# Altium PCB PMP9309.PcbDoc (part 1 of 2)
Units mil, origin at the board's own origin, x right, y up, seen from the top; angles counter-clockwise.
Board outline 7000 x 6500 mil, 4 copper layers (Top Layer, MidLayer1, MidLayer2, Bottom Layer), stack 90 mil thick; 176 components, 71 nets, 1187 pads, 29 vias.
Unrouted connection lines stored in the file: 1.
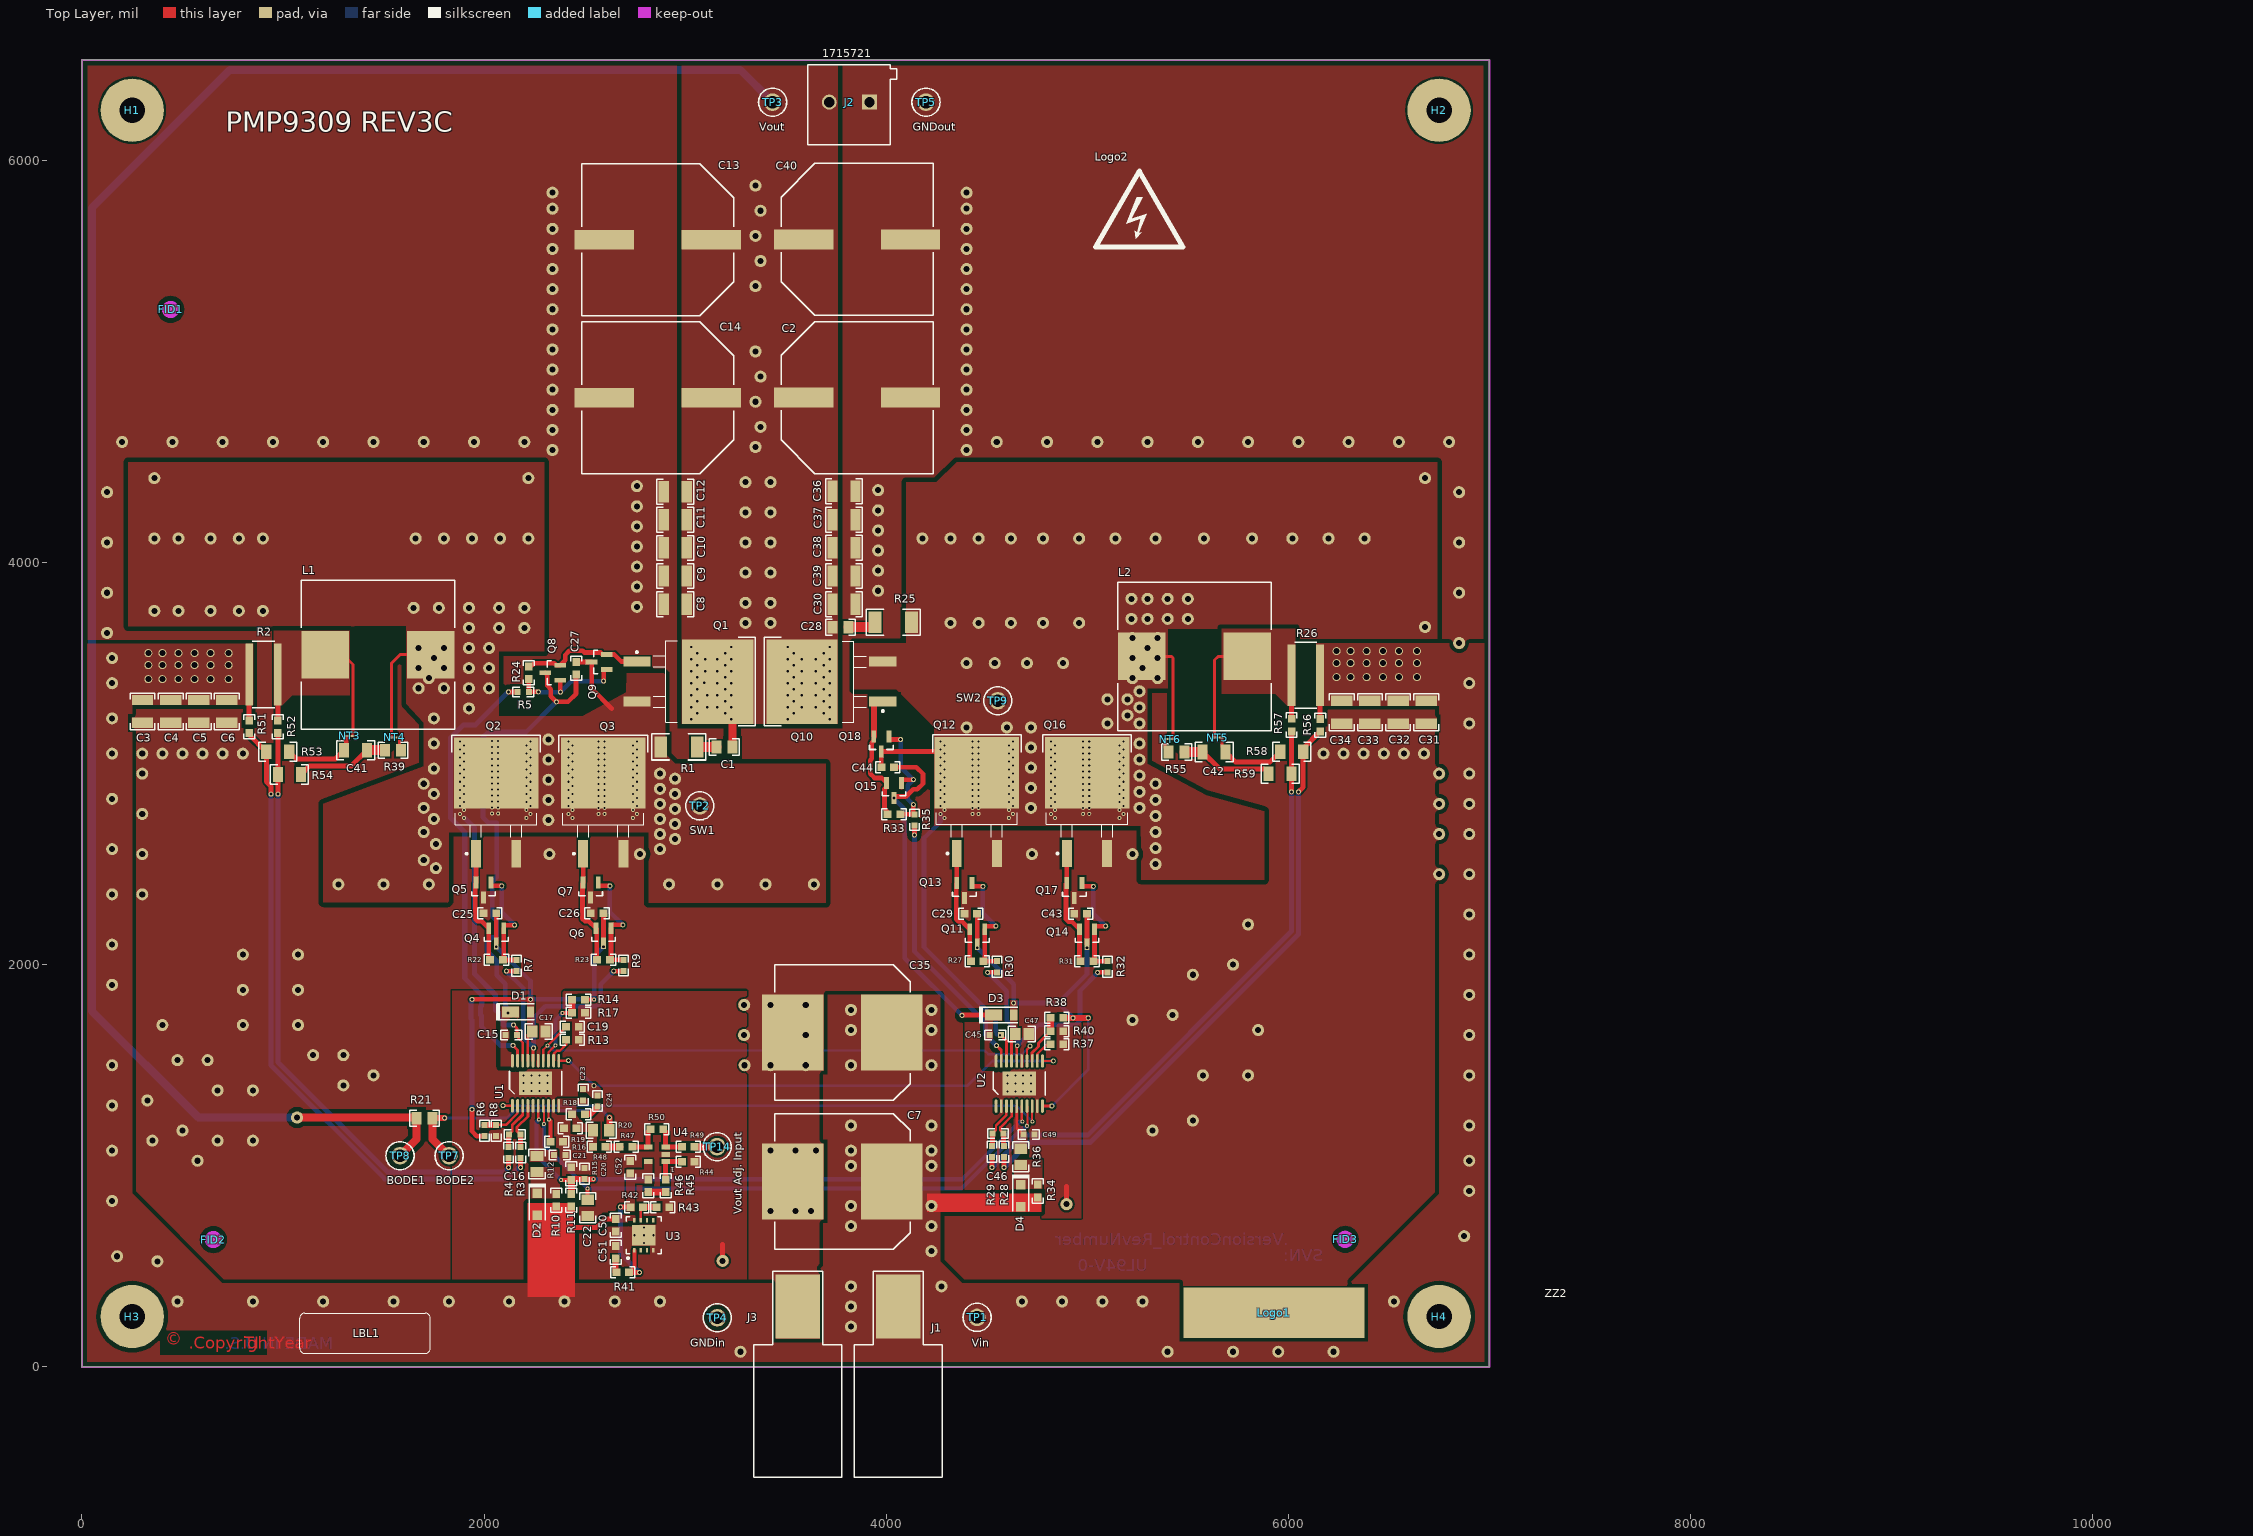
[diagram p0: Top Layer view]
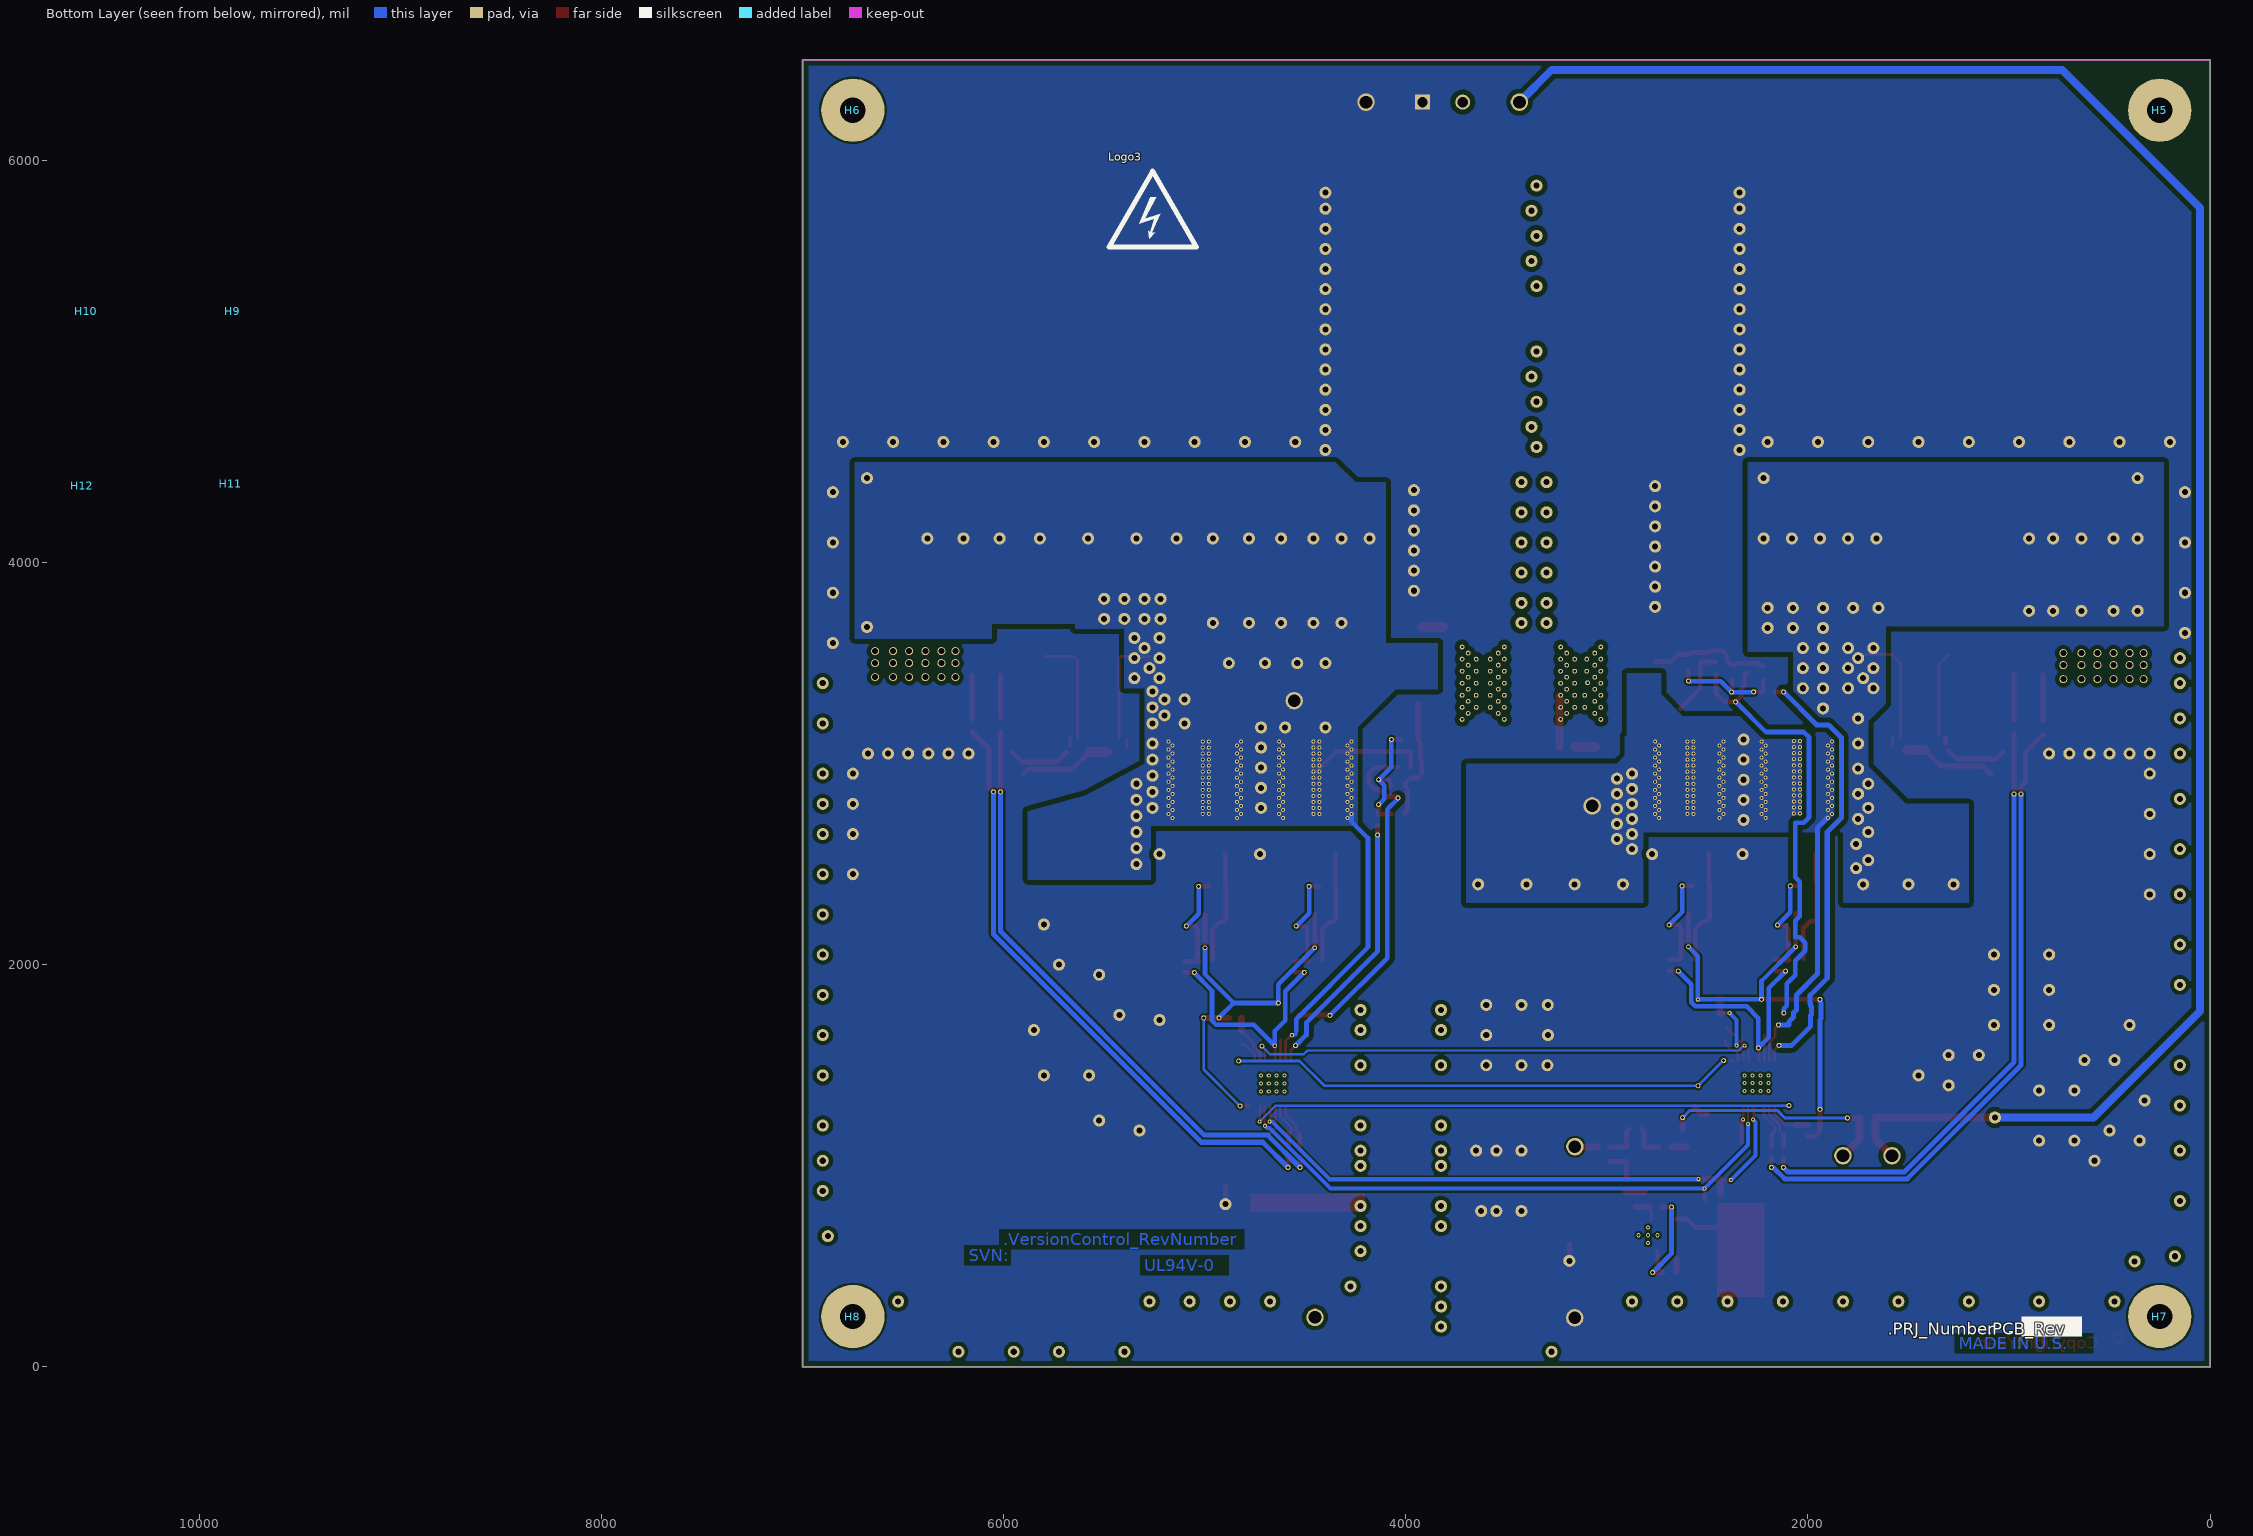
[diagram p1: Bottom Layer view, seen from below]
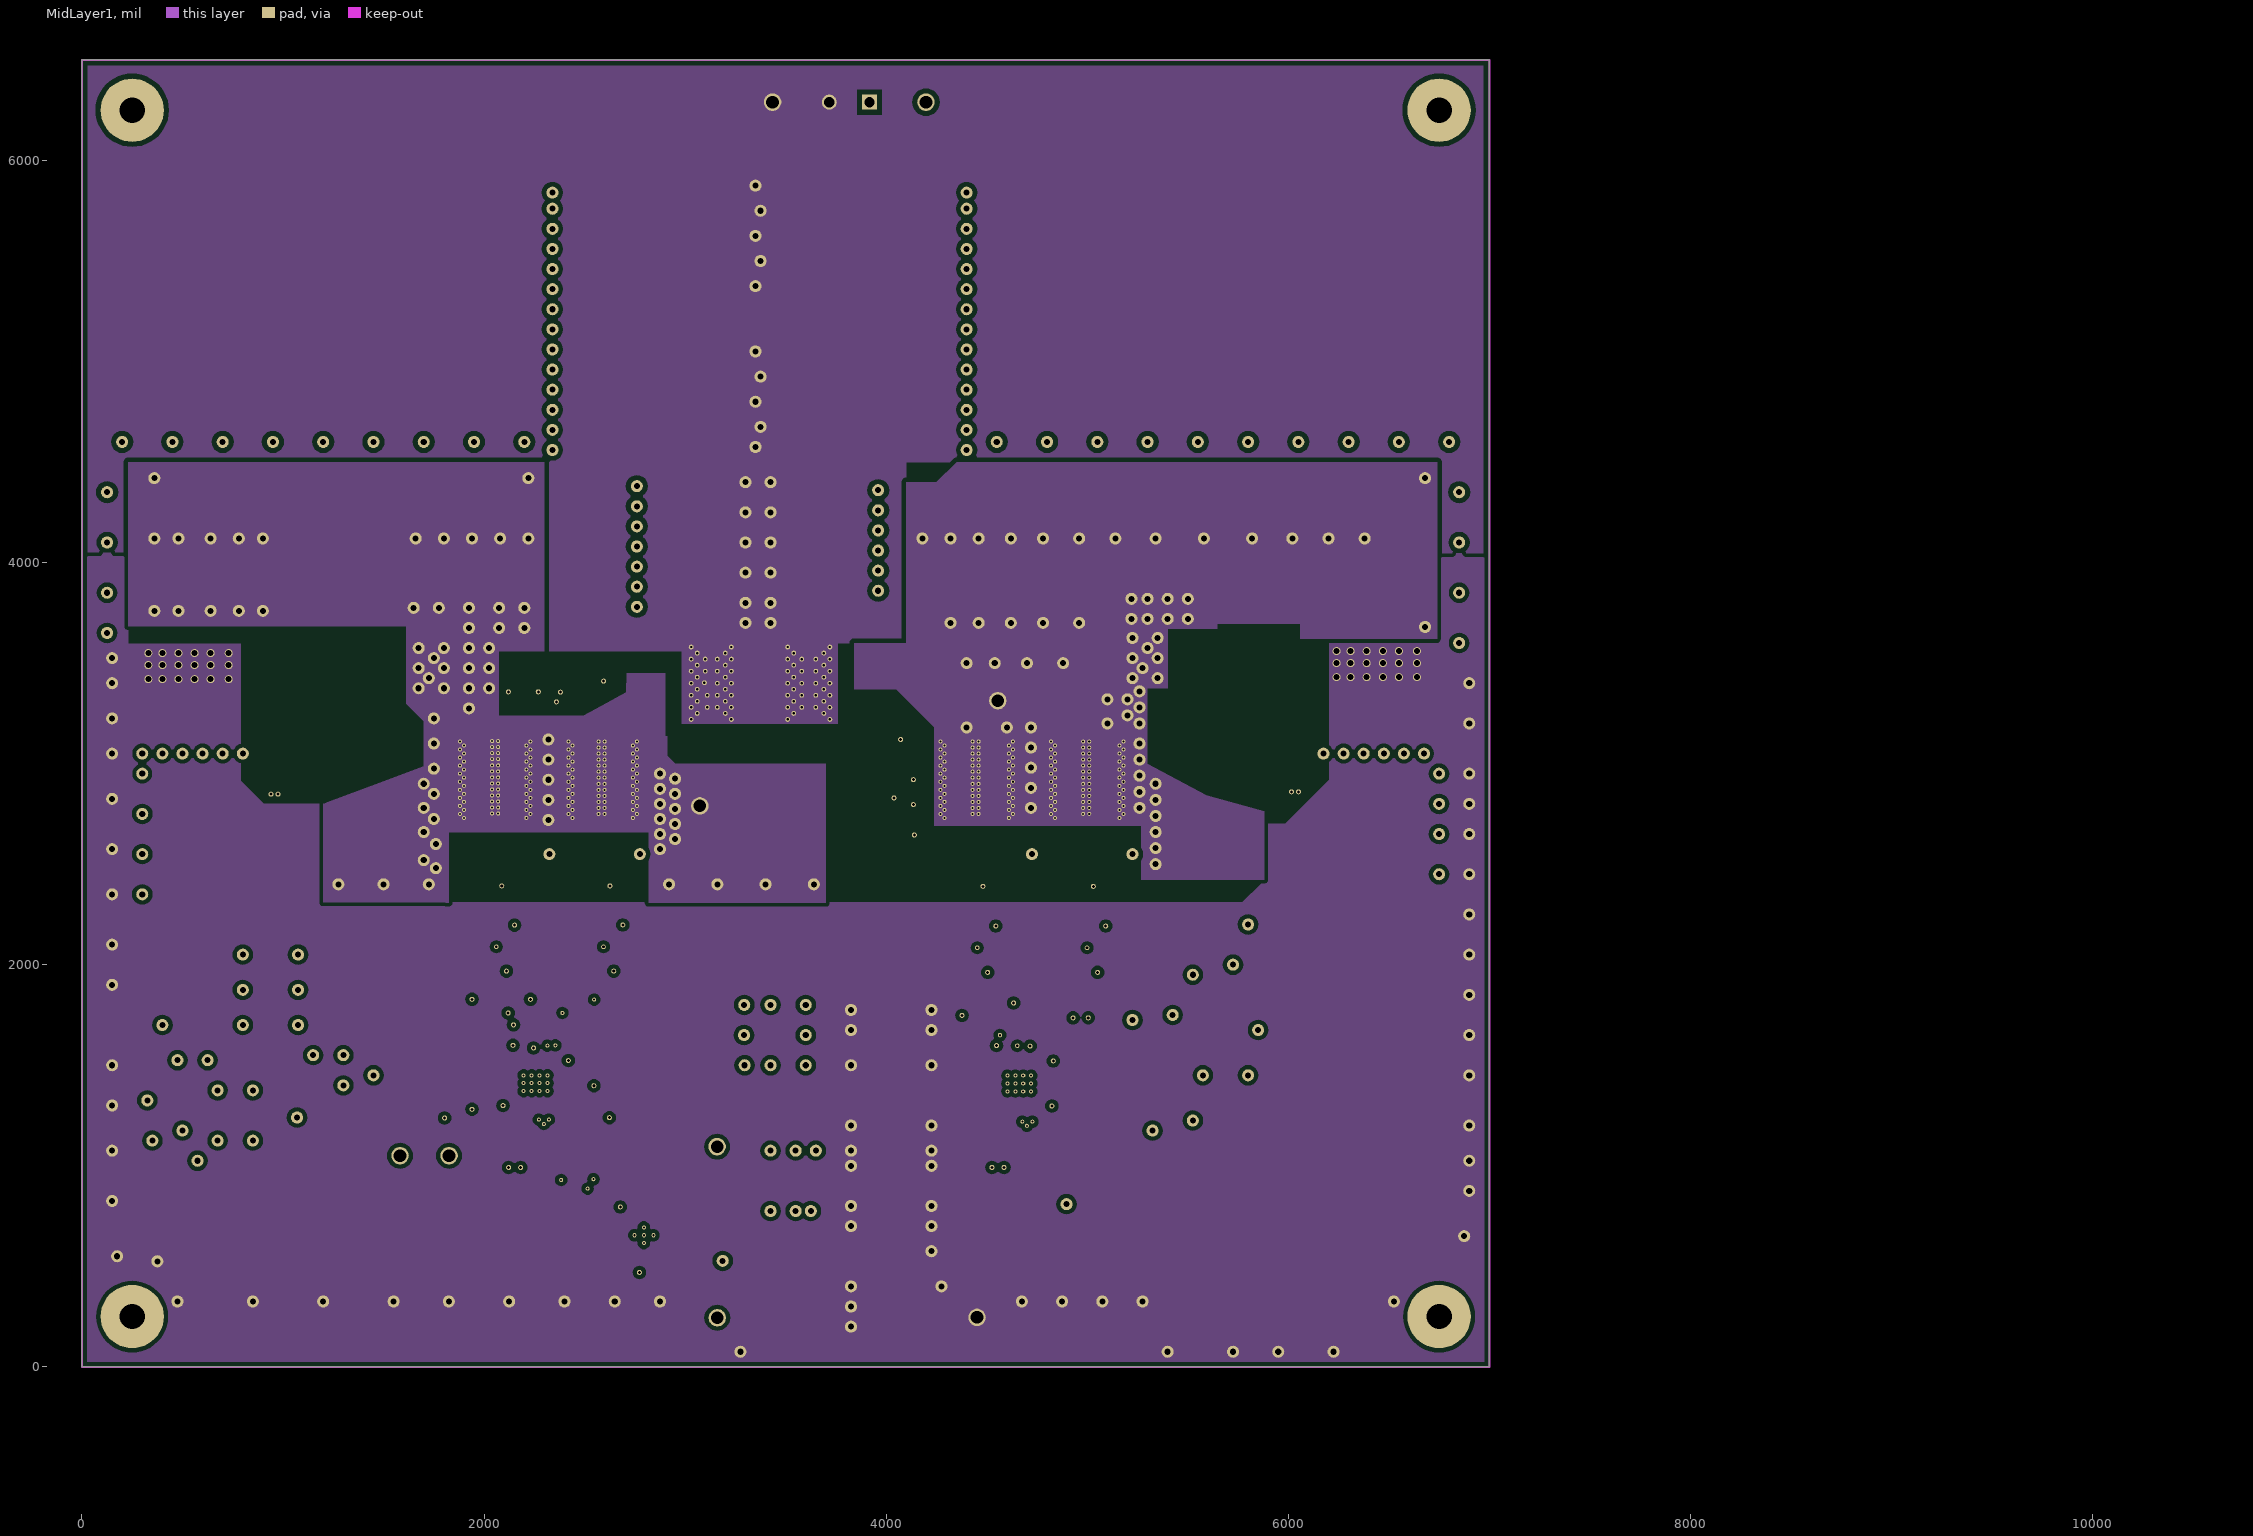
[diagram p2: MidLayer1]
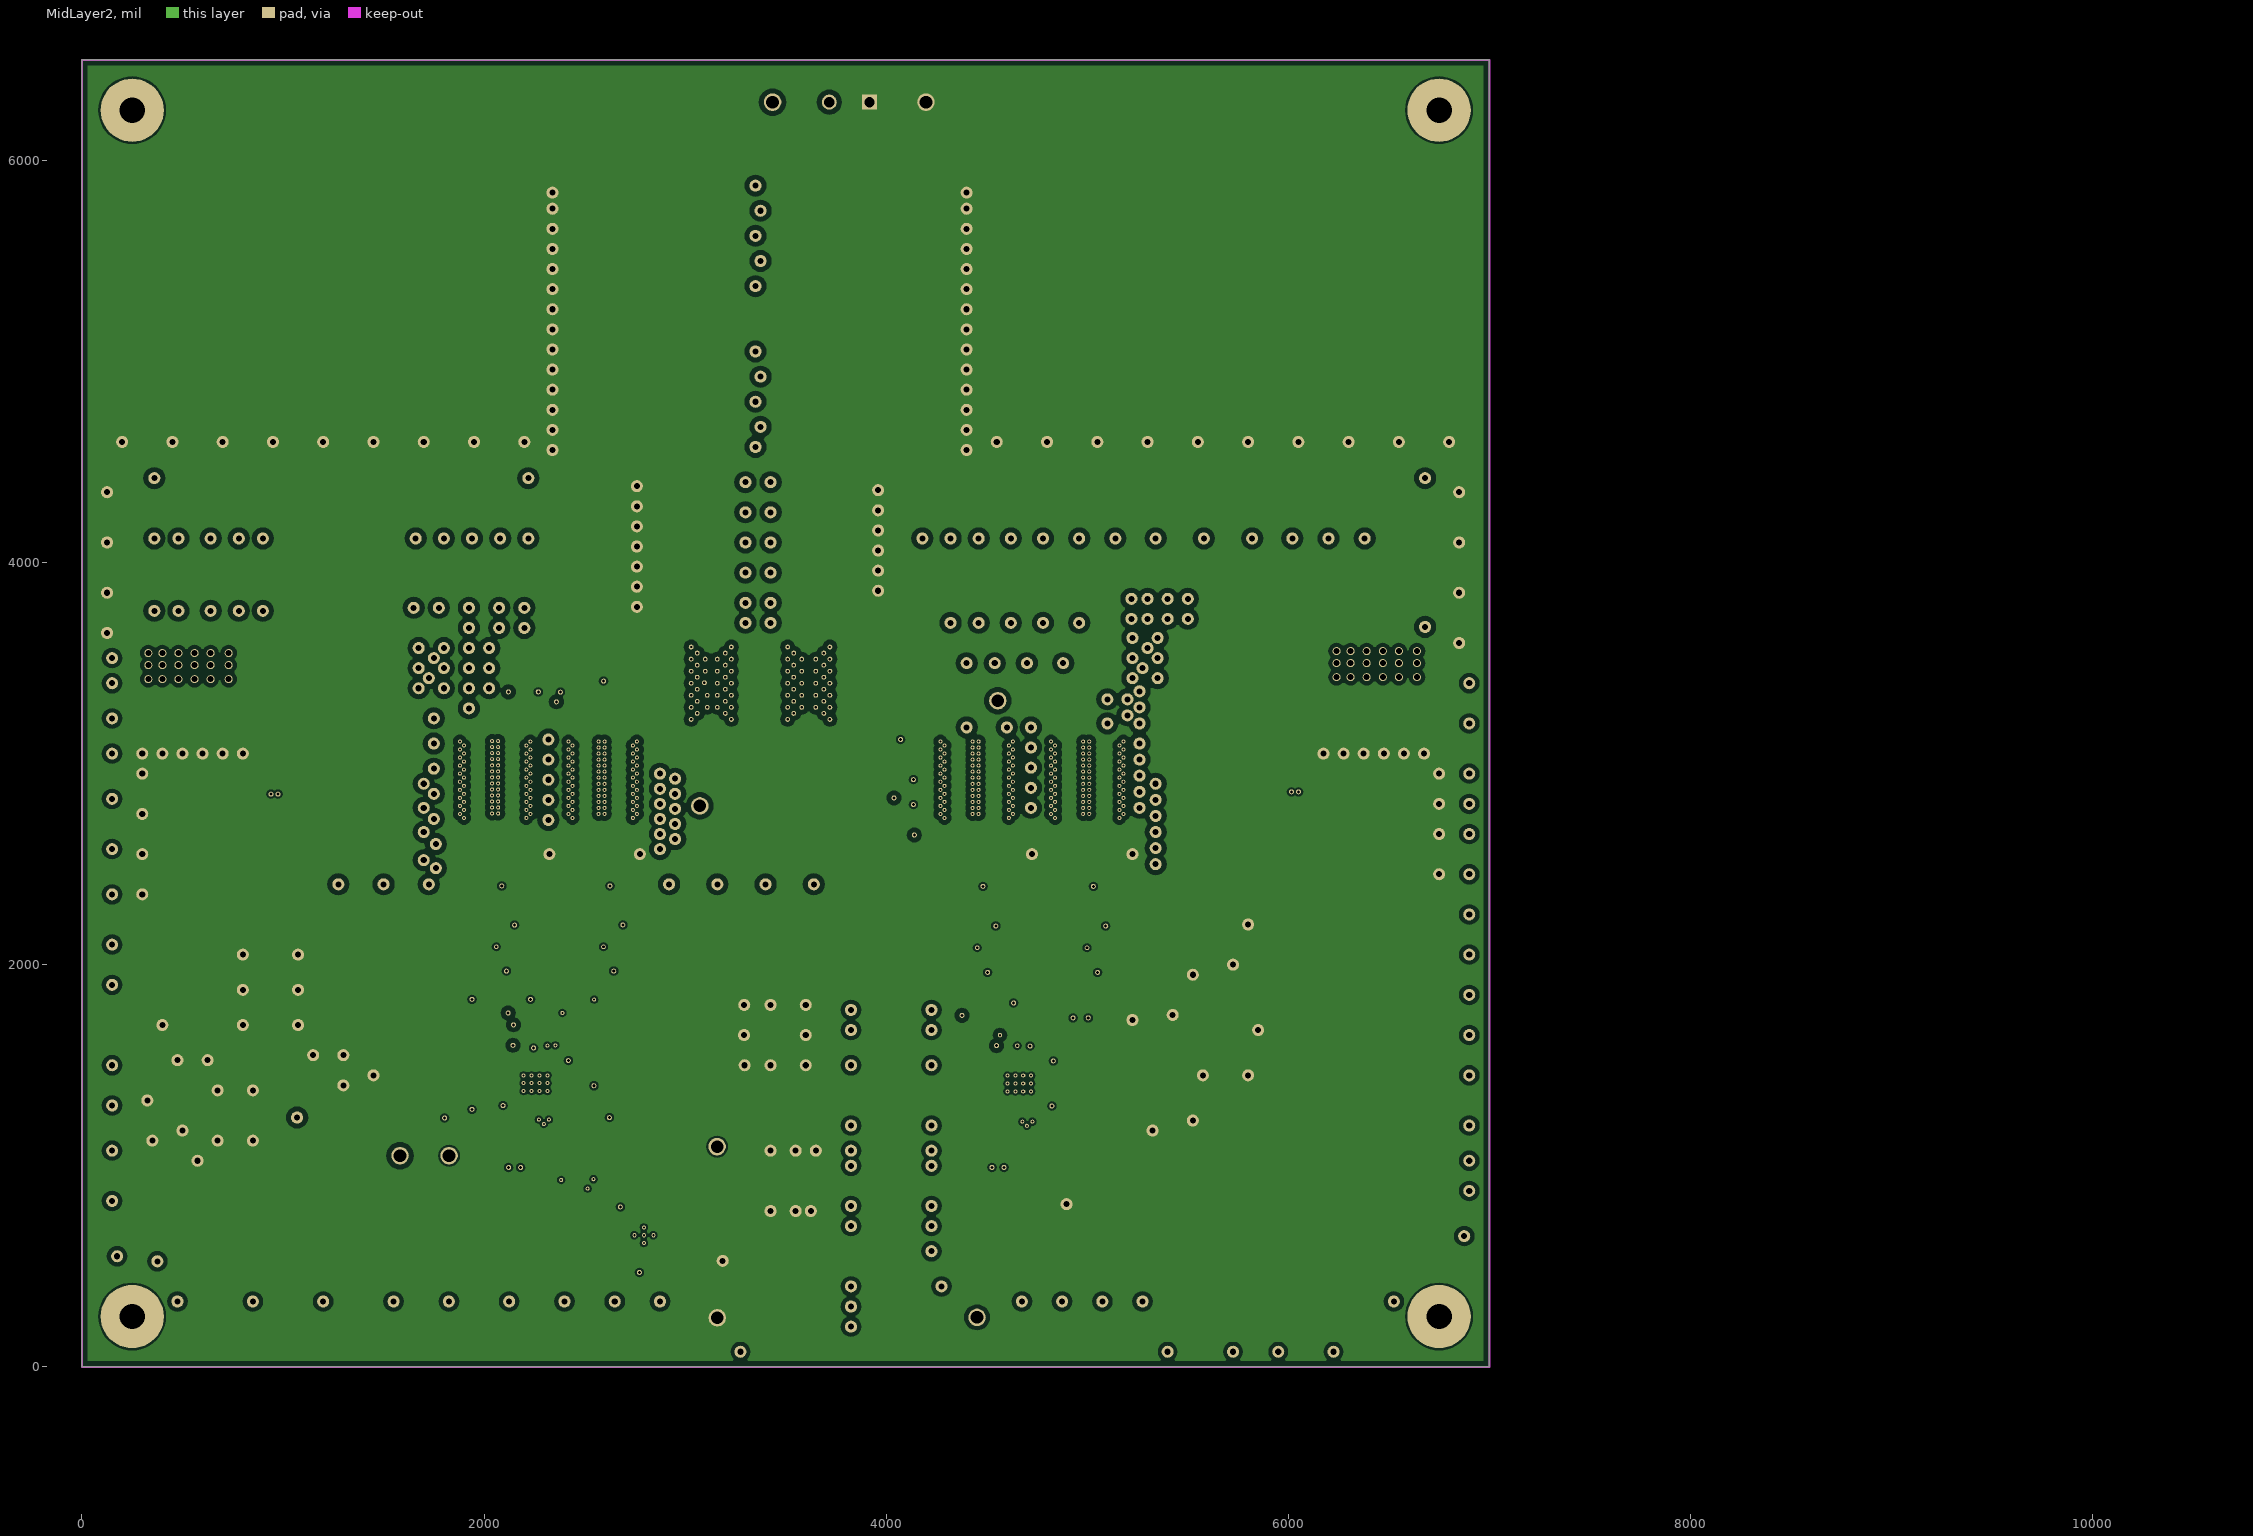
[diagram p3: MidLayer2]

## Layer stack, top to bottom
Top Layer: signal copper 1.4
Dielectric: core 59.2, FR-4, Dk 4.8
MidLayer1: signal copper 1.4
Dielectric: prepreg 12.6, FR-4, Dk 4.8
MidLayer2: signal copper 1.4
Dielectric: core 12.6, FR-4, Dk 4.8
Bottom Layer: signal copper 1.4

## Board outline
0,0 7000,0 7000,6500 0,6500

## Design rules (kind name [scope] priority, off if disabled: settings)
AcuteAngle [All] p1: minimum=4.50000000000000E+0001 checktracksonly=FALSE
AssemblyTestPointUsage [All] p1: valid=2
Clearance Clearance_VIN+X2 [InNet('VIN+X2')] p1: gap=11.8
Clearance Clearance_VIN+X1 [InNet('VIN+X1')] p2: gap=11.8
Clearance Clearance_VIN2 [InNet('VIN2')] p3: gap=11.8
Clearance Clearance_VIN1 [InNet('VIN1')] p4: gap=11.8
Clearance Clearance_VIN [InNet('VIN+')] p5: gap=20
Clearance Clearance_SW2 [InNet('SW2')] p6: gap=24
Clearance Clearance_SW1 [InNet('SW1')] p7: gap=24
Clearance Clearance_VOUT [InNet('VOUT')] p8: gap=24
Clearance Clearance_BST2 [InNet('BST2')] p9: gap=24
Clearance Clearance_BST1 [InNet('BST1')] p10: gap=24
Clearance Clearance_HO2 [InNet('HO2')] p11: gap=24
Clearance Clearance_HO1 [InNet('HO1')] p12: gap=24
Clearance Clearance_BoardEdge_MountingHoles [OnCopper and InComponentClass('Mounting Holes') vs IsKeepOut] p13: gap=24
Clearance Clearance_BoardEdge_Poly [OnCopper and InPoly vs IsKeepOut] p14: gap=24
Clearance Clearance_BoardEdge [OnCopper and Not InComponentClass('Logo') and not InComponentClass('FiducialMark') and not InRegion(1000,500,4000,800) and Not IsKeepout vs IsKeepOut] p15: gap=24
Clearance Clearance_Poly [InPolygon] p16: gap=10
Clearance [All] p17: gap=10
ComponentClearance ComponentClearance_Logo [InComponentClass('Logo')] p1: gap=50 collisioncheckmode=3 verticalgap=10 showdistances=FALSE
ComponentClearance ComponentClearance_ScrewToNut [(HasFootprint('NY PMS 440 0025 PH')) vs (HasFootprint('Keystone_1902C'))] p2: gap=5 collisioncheckmode=3 verticalgap=10 showdistances=FALSE
ComponentClearance ComponentClearance_MountingHoles [InComponentClass('Mounting Holes')] p3: gap=250 collisioncheckmode=3 verticalgap=100000 showdistances=FALSE
ComponentClearance ComponentClearance_SmallPassives [HasFootprint('0201*') or HasFootprint('0402*') or HasFootprint('0508') or HasFootprint('0603*') or HasFootprint('0612') or HasFootprint('0805*') or HasFootprint('0815*') or HasFootprint('0830*') or HasFootprint('1206*') or HasFootprint('1210*') or HasFootprint('1808*') or HasFootprint('1812*') or HasFootprint('1825*') or HasFootprint('2010*') or HasFootprint('2220*') or HasFootprint('2225*') or HasFootprint('2512*') or HasFootprint('2728*') or HasFootprint('3518*') vs HasFootprint('0201*') or HasFootprint('0402*') or HasFootprint('0508') or HasFootprint('0603*') or HasFootprint('0612') or HasFootprint('0805*') or HasFootprint('0815*') or HasFootprint('0830*') or HasFootprint('1206*') or HasFootprint('1210*') or HasFootprint('1808*') or HasFootprint('1812*') or HasFootprint('1825*') or HasFootprint('2010*') or HasFootprint('2220*') or HasFootprint('2225*') or HasFootprint('2512*') or HasFootprint('2728*') or HasFootprint('3518*')] p4: gap=20 collisioncheckmode=3 verticalgap=10 showdistances=FALSE
ComponentClearance ComponentClearance_THtoSMT [IsThruComponent vs IsSMTComponent] p5: gap=100 collisioncheckmode=3 verticalgap=30 showdistances=FALSE
ComponentClearance ComponentClearance_THtoTH [IsThruComponent vs IsThruComponent] p6: gap=118.11 collisioncheckmode=3 verticalgap=30 showdistances=FALSE
ComponentClearance [All] p7: gap=25 collisioncheckmode=3 verticalgap=10 showdistances=FALSE
DiffPairsRouting [All] p1: maxlimit=100 minlimit=10 mostfreqgap=10 maxuncoupledlength=1000
FabricationTestPointUsage TestPointUsage [All] p1: valid=2 allowmultiple=FALSE
FabricationTestpoint Testpoint [All] p1: side=3 testpointundercomponent=TRUE minsize=40 maxsize=100 preferedsize=60 minholesize=0 maxholesize=40 preferedholesize=32 testpointgrid=1 allowsidetop=TRUE allowsidebottom=TRUE usegrid=TRUE gridtolerance=0.01
FanoutControl Fanout_LCC [IsLCC] p1: bgadir=Out bgaviamode=Centered fanoutstyle=Auto fanoutdirection=Alternating viagrid=1 // Fanout_LCC (Default Rule)
FanoutControl Fanout_BGA [IsBGA] p2: bgadir=Out bgaviamode=Centered fanoutstyle=Auto fanoutdirection=Alternating viagrid=1 // Fanout_BGA (Default Rule)
FanoutControl Fanout_Default [All] p4: bgadir=Out bgaviamode=Centered fanoutstyle=Auto fanoutdirection=Alternating viagrid=1 // Fanout_Default (Default Rule)
FanoutControl Fanout_Small [(CompPinCount < 5)] p5: bgadir=Out bgaviamode=Centered fanoutstyle=Auto fanoutdirection=OutThenIn viagrid=1 // Fanout_Small (Default Rule)
HoleSize [All] p1: absolutevalues=TRUE maxlimit=251 minlimit=10 maxpercent=80.000 minpercent=20.000
MinimumAnnularRing MinimumAnnularRing_ThermalPadVias [IsVia and InAnyComponent] p1: minimumring=5.91
MinimumAnnularRing [All] p2: minimumring=5
MinimumSolderMaskSliver MinimumSolderMaskSliver_Logo [InComponentClass('Logo') vs InComponentClass('Logo')] p1: minsoldermaskwidth=0.7
MinimumSolderMaskSliver [All] p2: minsoldermaskwidth=3.94
PlaneConnect [All] p1: planeconnectstyle=Direct reliefexpansion=10 reliefentries=4 reliefconductorwidth=10 reliefairgap=10
PolygonConnect [All] p1: connectstyle=Direct reliefconductorwidth=10 reliefentries=4 polygonreliefangle="90 Angle" airgapwidth=10
RoutingVias ThermalPadVias [IsVia and InAnyComponent] p1: holewidth=7.87 width=19.68 viastyle="Through Hole" minholewidth=7.87 minwidth=19.68 maxholewidth=12.99 maxwidth=23.62
RoutingVias [All] p2: holewidth=16 width=34 viastyle="Through Hole" minholewidth=7.87 minwidth=26 maxholewidth=40 maxwidth=65
SMDToCorner [All] p1: distance=30000
SilkToSilkClearance [All] p1: silktosilkclearance=5
SilkscreenOverComponentPads [All] p1: minsilkscreentomaskgap=5
SolderMaskExpansion [All] p1: expansion=1.97
Width [All] p1: maxlimit=100 minlimit=6 preferedwidth=10 checkconnectedcopper=TRUE
14 further rules are at their usual default settings.

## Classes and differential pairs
component class "PMP9309 Schematics": C1 C2 C3 C4 C5 C6 C7 C8 C9 C10 C11 C12 C13 C14 C15 C16 C17 C19 C20 C21 C22 C23 C24 C25 C26 C27 C28 C29 C30 C31 C32 C33 C34 C35 C36 C37 C38 C39 C40 C41 C42 C43 C44 C45 C46 C47 C49 C50 C51 C52 D1 D2 D3 D4 J1 J2 J3 L1 L2 Logo2 Logo3 NT3 NT4 NT5 NT6 Q1 Q2 Q3 Q4 Q5 Q6 Q7 Q8 Q9 Q10 Q11 Q12 Q13 Q14 Q15 Q16 Q17 Q18 R1 R2 R3 R4 R5 R6 R7 R8 R9 R10 R11 R12 R13 R14 R15 R16 R17 R18 R19 R20 R21 R22 R23 R24 R25 R26 R27 R28 R29 R30 R31 R32 R33 R34 R35 R36 R37 R38 R39 R40 R41 R42 R43 R44 R45 R46 R47 R48 R49 R50 R51 R52 R53 R54 R55 R56 R57 R58 R59 TP1 TP2 TP3 TP4 TP5 TP7 TP8 TP9 TP14 U1 U2 U3 U4
component class "Mounting Holes": H1 H2 H3 H4
component class Logo: Logo1
component class PMP9309_Hardware_ANSI-B: FID1 FID2 FID3 H1 H2 H3 H4 H5 H6 H7 H8 H9 H10 H11 H12 LBL1 Logo1 ZZ1 ZZ2 ZZ3 ZZ4
component class FiducialMark: FID1 FID2 FID3
component class AssemblyNote: ZZ1 ZZ2 ZZ3 ZZ4
component class Label: LBL1

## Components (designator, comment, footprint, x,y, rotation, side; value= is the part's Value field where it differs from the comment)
C1 "GRM2165C2A471JA01D" 0805_HV 3195,3083 r0 top
C2 "EEV-FK2A331M" SM_RADIAL_K16 3855,4821 r0 top
C3 "GRM32DR71H335KA88L" 1210 301,3260 r270 top
C4 "GRM32DR71H335KA88L" 1210 441,3260 r270 top
C5 "GRM32DR71H335KA88L" 1210 581,3260 r270 top
C6 "GRM32DR71H335KA88L" 1210 721,3260 r270 top
C7 "EMVY500GTR331MLH0S" CAPSMT_62_LH0 3782,922 r180 top
C8 "GRM32CR72A105KA35L" 1210 2951,3793 r180 top
C9 "GRM32CR72A105KA35L" 1210 2951,3933 r180 top
C10 "GRM32CR72A105KA35L" 1210 2951,4073 r180 top
C11 "GRM32CR72A105KA35L" 1210 2951,4213 r180 top
C12 "GRM32CR72A105KA35L" 1210 2951,4353 r180 top
C13 "EEV-FK2A331M" SM_RADIAL_K16 2864,5606 r180 top
C14 "EEV-FK2A331M" SM_RADIAL_K16 2864,4820 r180 top
C15 "GRM188R72A104KA35D" 0603_HV 2135.52,1651.12 r180 top
C16 "C1608C0G2A101J" 0603_HV 2152.37,1156.18 r0 top
C17 "GRM21BR71C475KA73L" 0805 2272.52,1668.12 r180 top
C19 "GRM188R71E474KA12D" 0603 2439.52,1691.12 r0 top
C20 "GRM1885C1H101JA01D" 0603_HV 2499.06,961.12 r90 top
C21 "GRM188R71E474KA12D" 0603_HV 2376,1054 r0 top
C22 "GRM219R71E105KA88D" 0805_HV 2515,791 r270 top
C23 "C0603C331K5RACTU" 0603_HV 2493,1353 r90 top
C24 "C0603X223K5RACTU" 0603_HV 2565,1322 r90 top
C25 "DNP" 0603 2029,2257 r180 top
C26 "DNP" 0603 2562,2257 r180 top
C27 "DNP" 0603 2457.56,3474.44 r90 top
C28 "GRM2165C2A471JA01D" 0805_HV 3773,3679 r180 top
C29 "DNP" 0603 4421,2254 r180 top
C30 "GRM32CR72A105KA35L" 1210 3790,3793 r0 top
C31 "GRM32DR71H335KA88L" 1210 6686,3256 r270 top
C32 "GRM32DR71H335KA88L" 1210 6546,3256 r270 top
C33 "GRM32DR71H335KA88L" 1210 6406,3256 r270 top
C34 "GRM32DR71H335KA88L" 1210 6266,3256 r270 top
C35 "EMVY500GTR331MLH0S" CAPSMT_62_LH0 3782,1662 r180 top
C36 "GRM32CR72A105KA35L" 1210 3790,4354.31 r0 top
C37 "GRM32CR72A105KA35L" 1210 3790,4213.31 r0 top
C38 "GRM32CR72A105KA35L" 1210 3790,4073.31 r0 top
C39 "GRM32CR72A105KA35L" 1210 3790,3933.31 r0 top
C40 "EEV-FK2A331M" SM_RADIAL_K16 3855,5607 r0 top
C41 "GRM31CR71H225KA88L" 1206 1360.59,3067 r180 top
C42 "GRM31CR71H225KA88L" 1206 5630.69,3058 r0 top
C43 "DNP" 0603 4967,2254 r180 top
C44 "DNP" 0603 4008,2983 r180 top
C45 "GRM188R72A104KA35D" 0603_HV 4542,1649.68 r180 top
C46 "C1608C0G2A101J" 0603_HV 4556,1160 r0 top
C47 "GRM21BR71C475KA73L" 0805 4675,1656 r180 top
C49 "GRM188R71E474KA12D" 0603_HV 4710,1155 r0 top
C50 "06035C104KAT2A" 0603 2654.52,704.43 r270 top
C51 "GRM188R71A225KE15D" 0603 2654.52,569.43 r90 top
C52 "C0603C474K4RACTU" 0603 2726.52,993.12 r90 top
D1 "DFLS1100-7" powerDI123 2181.52,1765.12 r0 top
D2 "DNP" SOD-123F 2264.06,808.12 r270 top
D3 "DFLS1100-7" powerDI123 4584,1749.68 r0 top
D4 "DNP" SOD-123F 4669,851.68 r270 top
FID1 "Fiducial" Fiducial10-20 441,5259 r0 top
FID2 "Fiducial" Fiducial10-20 654,633 r0 top
FID3 "Fiducial" Fiducial10-20 6283,634 r0 top
H1 "NY PMS 440 0025 PH" "NY PMS 440 0025 PH" 250,6250 r0 top locked
H2 "NY PMS 440 0025 PH" "NY PMS 440 0025 PH" 6750,6250 r0 top locked
H3 "NY PMS 440 0025 PH" "NY PMS 440 0025 PH" 250,250 r0 top locked
H4 "NY PMS 440 0025 PH" "NY PMS 440 0025 PH" 6750,250 r0 top locked
H5 "1902C" Keystone_1902C 250,6250 r180 bottom locked
H6 "1902C" Keystone_1902C 6750,6250 r180 bottom locked
H7 "1902C" Keystone_1902C 250,250 r180 bottom locked
H8 "1902C" Keystone_1902C 6750,250 r180 bottom locked
H9 "SJ-5303 (CLEAR)" Bumpon_SJ5003Transparent 9834,5251 r180 bottom
H10 "SJ-5303 (CLEAR)" Bumpon_SJ5003Transparent 10564,5251 r180 bottom
H11 "SJ-5303 (CLEAR)" Bumpon_SJ5003Transparent 9844,4391 r180 bottom
H12 "SJ-5303 (CLEAR)" Bumpon_SJ5003Transparent 10584,4381 r180 bottom
J1 "6091" 6091 4060,300 r90 top
J2 "1715721" PhoenixContact_1715721 3817,6290 r180 top
J3 "6092" 6092 3560,300 r90 top
L1 "74435571100" WE-HCB_1890 1473,3542 r0 top
L2 "74435571100" WE-HCB_1890 5533,3533 r0 top
LBL1 "Size: 0.65\" x 0.20 \"" Label_650x200 1408,167 r0 top
Logo1 "Texas Instruments" TI_Stacked_SolderMask_Small 5928,269 r0 top
Logo2 "DANGER HIGH VOLTAGE" IEC_HighVoltage_Medium 5259,5746 r0 top
Logo3 "DANGER HIGH VOLTAGE" IEC_HighVoltage_Medium 5259,5746 r180 bottom
NT3 "Net-Tie" Net-Tie_10milWide_30milLong 1333,3138 r0 top net-tie
NT4 "Net-Tie" Net-Tie_10milWide_30milLong 1555,3131 r180 top net-tie
NT5 "Net-Tie" Net-Tie_10milWide_30milLong 5648,3129 r180 top net-tie
NT6 "Net-Tie" Net-Tie_10milWide_30milLong 5412,3122 r0 top net-tie
Q1 "SUM40N15-38" DDPAK 3006,3408 r0 top
Q2 "SUM40N15-38" DDPAK 2060,2798 r90 top
Q3 "SUM40N15-38" DDPAK 2593,2798 r90 top
Q4 "DNP" SOT-23 2061,2143.69 r270 top
Q5 "DNP" SOT-23 1997,2371 r270 top
Q6 "DNP" SOT-23 2594,2144 r270 top
Q7 "DNP" SOT-23 2530,2371 r270 top
Q8 "DNP" SOT-23 2341.56,3452.44 r180 top
Q9 "DNP" SOT-23 2572.56,3505.44 r180 top
Q10 "SUM40N15-38" DDPAK 3737,3408 r180 top
Q11 "DNP" SOT-23 4453,2138.98 r270 top
Q12 "SUM40N15-38" DDPAK 4451,2799 r90 top
Q13 "DNP" SOT-23 4389,2369 r270 top
Q14 "DNP" SOT-23 4999,2139 r270 top
Q15 "DNP" SOT-23 4039,2867 r270 top
Q16 "SUM40N15-38" DDPAK 4999,2799 r90 top
Q17 "DNP" SOT-23 4936,2369 r270 top
Q18 "DNP" SOT-23 3976,3098 r270 top
R1 "8.2" 2010 2969,3083 r180 top
R2 "KRL7638-C-R004-F-T1" 3015 902.99,3443.35 r180 top
R3 "CRCW0603100RFKEA" 0603_HV 2182.37,1066.18 r270 top
R4 "CRCW0603100RFKEA" 0603_HV 2122.37,1066.18 r270 top
R5 "ERJ-3GEY0R00V" 0603_HV 2195,3357 r180 top
R6 "DNP" 0603_HV 2001.52,1175.12 r270 top
R7 "ERJ-3GEY0R00V" 0603_HV 2161,1995.69 r90 top
R8 "ERJ-3GEY0R00V" 0603_HV 2060.52,1175.12 r90 top
R9 "ERJ-3GEY0R00V" 0603_HV 2693,1996 r270 top
R10 "ERJ-3GEY0R00V" 0603 2359.06,828.12 r270 top
R11 "CRCW0603100KFKEA" 0603 2434.06,828.12 r270 top
R12 "CRCW08052R20JNEA" 0805_HV 2263.32,1008.5 r270 top
R13 "CRCW060336K5FKEA" 0603 2439.52,1627.12 r180 top
R14 "ERJ-3GEY0R00V" 0603 2469.52,1826.12 r0 top
R15 "CRCW06037K68FKEA" 0603 2434.06,961.12 r270 top
R16 "CRCW060336K5FKEA" 0603 2361,1119 r180 top
R17 "DNP" 0603 2469.52,1760.12 r180 top
R18 "CRCW060368K1FKEA" 0603 2469.52,1256.42 r0 top
R19 "CRCW0603750RFKEA" 0603 2428.52,1187.12 r180 top
R20 "CRCW080551K1FKEA" 0805_HV 2582.52,1177.12 r0 top
R21 "CRCW0805825RFKEA" 0805_HV 1704,1237 r0 top
R22 "CRCW060349R9FKEA" 0603 2062,2023.69 r180 top
R23 "CRCW060349R9FKEA" 0603 2594,2024 r180 top
R24 "CRCW060349R9FKEA" 0603 2222.56,3452.44 r90 top
R25 "8.2" 2010 4035,3704 r0 top
R26 "KRL7638-C-R004-F-T1" 3015 6087,3440 r0 top
R27 "CRCW060349R9FKEA" 0603 4453,2017.98 r180 top
R28 "CRCW0603100RFKEA" 0603_HV 4586.18,1070.5 r270 top
R29 "CRCW0603100RFKEA" 0603_HV 4526.18,1070.5 r270 top
R30 "ERJ-3GEY0R00V" 0603_HV 4552,1989.98 r90 top
R31 "CRCW060349R9FKEA" 0603 4999,2018 r180 top
R32 "ERJ-3GEY0R00V" 0603_HV 5100,1990 r270 top
R33 "CRCW060349R9FKEA" 0603 4039,2748 r180 top
R34 "ERJ-3GEY0R00V" 0603 4754,874.68 r270 top
R35 "ERJ-3GEY0R00V" 0603_HV 4140,2720 r270 top
R36 "CRCW08052R20JNEA" 0805_HV 4669,1044.68 r270 top
R37 "CRCW060336K5FKEA" 0603 4849,1603.68 r180 top
R38 "ERJ-3GEY0R00V" 0603 4849,1735.68 r0 top
R39 "CRCW0805825RFKEA" 0805_HV 1546.59,3067 r0 top
R40 "DNP" 0603 4849,1669.68 r180 top
R41 "CRCW06030000Z0EA" 0603 2689.52,469.43 r0 top
R42 "RT0603DRE0730K5L" 0603 2759.52,794.43 r180 top
R43 "CRCW060310K0FKEA" 0603 2889.52,794.43 r180 top
R44 "CRCW06031K00FKEA" 0603 3015.52,1020.12 r180 top
R45 "CRCW06032K00FKEA" 0603 2903.52,901.12 r270 top
R46 "CRCW06032K00FKEA" 0603 2816.52,901.12 r90 top
R47 "RC0603FR-07820RL" 0603 2706.52,1094.12 r180 top
R48 "RC0603FR-0756RL" 0603 2573.52,1094.12 r180 top
R49 "CRCW0603100KFKEA" 0603 3015.52,1094.12 r180 top
R50 "CRCW0603100KFKEA" 0603 2859.52,1182.12 r180 top
R51 "CRCW06030000Z0EA" 0603 831.99,3183.35 r90 top
R52 "CRCW06030000Z0EA" 0603 973.99,3183.35 r90 top
R53 "CRCW12060000Z0EA" 1206 973.99,3058.35 r0 top
R54 "CRCW12060000Z0EA" 1206 1031.99,2946.35 r0 top
R55 "CRCW0805825RFKEA" 0805_HV 5444.69,3058 r180 top
R56 "CRCW06030000Z0EA" 0603 6158,3191 r90 top
R57 "CRCW06030000Z0EA" 0603 6016,3192 r90 top
R58 "CRCW12060000Z0EA" 1206 6017,3059 r180 top
R59 "CRCW12060000Z0EA" 1206 5959,2950 r180 top
TP1 "Vin" Keystone5010 4452,246 r0 top
TP2 "SW1" Keystone5012 3073,2790 r0 top
TP3 "Vout" Keystone5010 3435,6290 r0 top
TP4 "GNDin" Keystone5011 3160,244 r0 top
TP5 "GNDout" Keystone5011 4198,6290 r0 top
TP7 "BODE2" Keystone5012 1826,1050 r0 top
TP8 "BODE1" Keystone5012 1582,1050 r0 top
TP9 "SW2" Keystone5012 4555,3313 r0 top
TP14 "Vout Adj. Input" Keystone5009 3159.04,1095 r0 top
U1 "LM5122MH" PWP0020A_N 2256.32,1410.5 r90 top
U2 "LM5122MH" PWP0020A_N 4662,1409 r90 top
U3 "LP2951CSD" SDC08A 2794.52,654.43 r90 top
U4 "LMV321DBV" SOT23-5P 2858.52,1057.12 r180 top
ZZ1 "This Assembly Note is for PCB labels only" AssemblyNoteLabel 5676,7708 r0 top
ZZ2 "These assemblies are ESD sensitive, ESD precautions shall be observed." AssemblyNote 7290,300 r90 top
ZZ3 "These assemblies must be clean and free from flux and all contaminants. Use of no clean flux is not acceptable." AssemblyNote 5676,7510.56 r0 top
ZZ4 "These assemblies must comply with workmanship standards IPC-A-610 Class 2, unless otherwise specified." AssemblyNote 5676,7422 r0 top

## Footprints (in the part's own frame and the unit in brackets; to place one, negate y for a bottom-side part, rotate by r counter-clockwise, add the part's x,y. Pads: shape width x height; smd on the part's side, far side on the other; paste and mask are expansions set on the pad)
0603 [mm] "0603 from SM-752 data"
  rect 1x0.95 smd: 1(-0.8,0) 2(0.8,0)
  silkscreen extent -1.52,-0.69 1.52,0.69, body extent -0.87,-0.47 0.87,0.47, height 0.85
0603_HV [mil] "Ernesto recommended land pattern.  26 mil between pads."
  rect 30x30 smd: 1(-28,0) 2(28,0)
  silkscreen extent -52,-24 52,24, body extent -34,-19 34,19, height 33
0805 [mm] "0805 from SM-752 data"
  rect 1.3x1.5 smd: 1(-0.85,0) 2(0.85,0)
  silkscreen extent -1.72,-0.97 1.72,0.97, body extent -1.1,-0.72 1.1,0.72, height 1.1
0805_HV [mil] "0805 with 30mil clearance between pads"
  rect 50x63 smd: 1(-40,0) 2(40,0)
  silkscreen extent -74,-40 74,40, body extent -43,-29 43,29, height 43
1206 [mm] "1206 from SM-752 data"
  rect 1.3x1.85 smd: 1(-1.45,0) 2(1.45,0)
  silkscreen extent -2.4,-1.21 2.4,1.21, body extent -1.7,-0.9 1.7,0.9, height 1.35
1210 [mm] "1210 from SM-752 data"
  rect 1.3x2.7 smd: 1(-1.45,0) 2(1.45,0)
  silkscreen extent -2.32,-1.57 2.32,1.57, body extent -1.7,-1.35 1.7,1.35, height 1.35
2010 [mm] "Chip Capacitor, Body 5.08x2.54mm, IPC Medium Density"
  rect 1.6x2.7 smd: 1(-2.3,0) 2(2.3,0)
  silkscreen extent -3.42,-1.65 3.42,1.65, body extent -2.73,-1.45 2.73,1.45, height 1.66
3015 [mm] "Susumu recommended land pattern"
  rect 1x7.8 smd: 1(-1.8,0) 2(1.8,0)
  silkscreen extent -1.4,-4.19 1.4,4.19, body extent -2,-3.9 2,3.9, height 0.7
6091 [mil] "Keystone Insulated End Launch Banana Jack"
  rect 320x220 smd: 1(0,0)
  silkscreen extent -850,-218 175,218, body extent -846,-216 91,216, height 227
6092 [mil] "Keystone Insulated End Launch Banana Jack"
  rect 320x220 smd: 1(0,0)
  silkscreen extent -850,-218 175,218, body extent -846,-216 91,216, height 227
AssemblyNote [mil] "Assembly Note"
AssemblyNoteLabel [mil] "Assembly Note for PCB Labels"
Bumpon_SJ5003Transparent [mil] "3M Hemispherical Bumpon transparent"
  round 1 on Mech4: 0(0,0)
  body extent -217,-218 219,218, height 197
CAPSMT_62_LH0 [mm] "16 x 16.5mm:  Chemi-Con LH0"
  rect 7.8x9.6 smd: 1(-6.25,0) 2(6.25,0)
  silkscreen extent -8.55,-8.55 8.55,8.55, body extent -8.55,-8.55 8.55,8.55, height 17
DDPAK [mil] "D2-PAK, 3-Pads, Body 9.7x10.4mm (max), TO-263AB, using Vishay Silionix recommended pad sizes"
  rect 135x49.49 smd: 1(-246.06,100) 3(-246.06,-100)
  rect 355x420 smd paste-181.1: 4(155.51,0)
  silkscreen extent -251,-220 344,220, body extent -295,-202 324,202, height 180
Fiducial10-20 [mm]
  round 1 smd paste-0.5 mask+0.5: 1(0,0)
  Top Layer keep-out circle w1.178: c0,0 r0.5
IEC_HighVoltage_Medium [mil]
  silkscreen extent -217,-176 217,200
Keystone5009 [mil] "Keystone Compact loops"
  round 87 hole 63: 1(0,0)
  silkscreen extent -70,-70 70,70, body extent -63,-63 62,63, height 225
Keystone5010 [mil] "Keystone Multipurpose loops"
  round 87 hole 63: 1(0,0)
  silkscreen extent -70,-70 70,70, body extent -63,-63 63,62, height 319
Keystone5011 [mil] "Keystone Multipurpose loops"
  round 87 hole 63: 1(0,0)
  silkscreen extent -70,-70 70,70, body extent -63,-63 63,62, height 319
Keystone5012 [mil] "Keystone Multipurpose loops"
  round 87 hole 63: 1(0,0)
  silkscreen extent -70,-70 70,70, body extent -63,-63 63,62, height 319
Keystone_1902C [mil] "Hex Standoff, 4-40 threaded, nylon"
  body extent -145,-126 146,126, height 501
Label_650x200 [mil] "Thermal Transfer Label"
  silkscreen extent -325,-100 325,100, body extent -326,-101 326,101, height 1
Net-Tie_10milWide_30milLong [mil] "10mil net tie, no solder mask opening, no solder paste"
  rect 30x10 smd paste-5 mask-5: 1(-15,0) 2(15,0)
"NY PMS 440 0025 PH" [mm] "4-40 nylon screw and mounting hole"
  round 8 hole 3.2: 1(0,0)
  body extent -3.3,-3.3 3.3,3.3, height 2.69
PhoenixContact_1715721 [mm] "Phoenix Contact 1715721 used on LM3445 design from Longmont"
  rect 1.905x1.905 hole 1.3: 1(-2.54,0)
  round 1.9 hole 1.3: 2(2.54,0)
  silkscreen extent -5.97,-4.75 5.28,5.36, body extent -5.82,-4.6 5.08,5.2, height 14.2
powerDI123 [mm] "Diodes Inc recommended land pattern, document number DS30628 Rev. 6-2"
  rect 2.2x1.4 smd: 1(-1.275,0)
  rect 0.9x1.4 smd: 2(1.275,0)
  silkscreen extent -3.1,-1.09 1.76,1.09, body extent -2.38,-0.97 1.52,0.96, height 1
PWP0020A_N [mm] "TSOP, 20-Leads, Body 6.5x4.4mm, Pitch 0.65mm, Exposed Pad, IPC Medium Density"
  oval 1.7x0.35 smd: 1(-2.85,2.925) 2(-2.85,2.275) 3(-2.85,1.625) 4(-2.85,0.975) 5(-2.85,0.325) 6(-2.85,-0.325) 7(-2.85,-0.975) 8(-2.85,-1.625) 9(-2.85,-2.275) 10(-2.85,-2.925) 11(2.85,-2.925) 12(2.85,-2.275) 13(2.85,-1.625) 14(2.85,-0.975) 15(2.85,-0.325) 16(2.85,0.325) 17(2.85,0.975) 18(2.85,1.625) 19(2.85,2.275) 20(2.85,2.925)
  rect 3x4.2 smd: 21(0,0)
  silkscreen extent -1.5,-3.3 1.5,3.3, body extent -3.21,-3.25 3.21,3.25, height 0.98
SDC08A [mm] "SON, 8-Leads, Body 4x4mm, Pitch 0.8mm, NSC Recommended"
  rect 0.6x0.3 smd paste-0.15 mask+0.051: 1(-1.9,1.2) 2(-1.9,0.4) 3(-1.9,-0.4) 4(-1.9,-1.2) 5(1.9,-1.2) 6(1.9,-0.4) 7(1.9,0.4) 8(1.9,1.2)
  rect 2.6x3 smd paste-1.5 mask+0.051: 9(0,0)
  silkscreen extent -3.02,-2.2 2.35,2.2, body extent -2.05,-2.05 2.05,2.05, height 0.8
SM_RADIAL_K16 [mm] "18 x 16.5mm:  Panasonic K16 (K18 from land pattern recommendation)"
  rect 7.5x2.5 smd: 1(-6.75,0) 2(6.75,0)
  silkscreen extent -9.6,-9.6 9.6,9.6, body extent -9.6,-9.6 9.6,9.6, height 17
SOD-123F [mm] "NXP recommended land pattern"
  rect 1.2x1.2 smd paste-0.05: 1(-1.4,0) 2(1.4,0)
  silkscreen extent -2.64,-1.12 2.01,1.12, body extent -1.8,-0.85 1.8,0.85, height 1.2
SOT23-5P [mil]
  rect 42x25 smd: 1(-45,37) 2(-45,0) 3(-45,-37) 4(42,-37) 5(42,37)
SOT-23 [mm] "SOT23, 3-Leads, Body 2.9x1.3mm, Pitch 0.95mm, Lead Span 2.5mm, IPC Medium Density"
  rect 1.5x0.6 smd: 1(-0.95,0.95) 2(-0.95,-0.95) 3(0.95,0)
  silkscreen extent 0.2,-1.5 0.7,1.5, body extent -1.16,-1.45 1.21,1.45, height 1
TI_Stacked_SolderMask_Small [mil]
  rect 900x250 smd paste-125 mask-125: 0(0,0)
WE-HCB_1890 [mm] "WURTH ELEKTRONIK"
  rect 6x6 smd: 1(-6.65,0) 2(6.65,0)
  silkscreen extent -9.7,-9.4 9.7,9.4, body extent -9.65,-9.35 9.65,9.35, height 9.2

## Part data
C1 C28: "CAP, CERM, 470pF, 100V, +/-5%, C0G/NP0, 0805"
C2 C13 C14 C40: "CAP, AL, 330uF, 100V, +/-20%, 0.153 ohm, SMD"
C3 C4 C5 C6 C31 C32 C33 C34: "CAP, CERM, 3.3uF, 50V, +/-10%, X7R, 1210"
C7 C35: "CAP, AL, 330uF, 50V, +/-20%, 0.087 ohm, SMD"
C8 C9 C10 C11 C12 C30 C36 C37 C38 C39: "CAP, CERM, 1uF, 100V, +/-10%, X7R, 1210"
C15 C45: "CAP, CERM, 0.1uF, 100V, +/-10%, X7R, 0603"
C16 C46: "CAP, CERM, 100pF, 100V, +/-5%, C0G/NP0, 0603"
C17 C47: "CAP, CERM, 4.7uF, 16V, +/-10%, X7R, 0805"
C19 C21 C49: "CAP, CERM, 0.47uF, 25V, +/-10%, X7R, 0603"
C20: "CAP, CERM, 100pF, 50V, +/-5%, C0G/NP0, 0603"
C22: "CAP, CERM, 1uF, 25V, +/-10%, X7R, 0805"
C23: "CAP, CERM, 330pF, 50V, +/-10%, X7R, 0603"
C24: "CAP, CERM, 0.022uF, 50V, +/-10%, X7R, 0603"
C25 C26 C27 C29 C43 C44: library part GRM188R71E105KA12D, "CAP, CERM, 1uF, 25V, +/-10%, X7R, 0603"
C41 C42: "CAP, CERM, 2.2uF, 50V, +/-10%, X7R, 1206"
C50: "CAP, CERM, 0.1uF, 50V, +/-10%, X7R, 0603"
C51: "CAP, CERM, 2.2uF, 10V, +/-10%, X7R, 0603"
C52: "CAP, CERM, 0.47uF, 16V, +/-10%, X7R, 0603"
D1 D3: "Diode, Schottky, 100V, 1A, PowerDI123"
D2 D4: library part PMEG6010CEH,115, "Diode, Schottky, 60V, 1A, SOD-123F"
FID1 FID2 FID3: "Fiducial mark.  There is nothing to buy or mount."
H1 H2 H3 H4: "Machine Screw, Round, #4-40 x 1/4, Nylon, Philips panhead"
H5 H6 H7 H8: "Standoff, Hex, 0.5\"L #4-40 Nylon"
H9 H10 H11 H12: "Bumpon, Hemisphere, 0.44 X 0.20, Clear"
J1: "Standard Banana Jack, Insulated, Red"
J2: "Conn Term Block, 2POS, 5.08mm, TH"
J3: "Standard Banana Jack, Insulated, Black"
L1 L2: "Inductor, Shielded Drum Core, Ferrite, 10uH, 16.5A, 0.0069 ohm, SMD"
LBL1: library part THT-14-423-10, "Thermal Transfer Printable Labels, 0.650\" W x 0.200\" H - 10,000 per roll"
Logo1: library part TI_Logo, "Texas Instrument Corporate Signature"
Logo2 Logo3: library part IEC_HighVoltage, "IEC 61010-1 High Voltage Warning"
NT3 NT4 NT5 NT6: "Single point connection between nets."
Q1 Q2 Q3 Q10 Q12 Q16: "MOSFET, N-CH, 150V, 40A, DDPAK"
Q4 Q6 Q8 Q11 Q14 Q15: library part "MMBT3904, Fairchild Semiconductor", "Transistor, NPN, 40V, 0.2A, SOT-23"
Q5 Q7 Q9 Q13 Q17 Q18: library part "MMBT3906, Fairchild Semiconductor", "Transistor, PNP, 40V, 0.2A, SOT-23"
R1 R25: library part CRCW20108R20JNEF, "RES 8.2 OHM 3/4W 5% 2010 SMD"
R2 R26: "RES, 0.004 ohm, 1%, 4W, 3015 WIDE"
R3 R4 R28 R29: "RES, 100 ohm, 1%, 0.1W, 0603"
R5 R7 R8 R9 R10 R14 R30 R32 R34 R35 R38 R41 R51 R52 R56 R57: "RES, 0 ohm, 5%, 0.1W, 0603"
R6 R17 R40: library part ERJ-3GEY0R00V, "RES, 0 ohm, 5%, 0.1W, 0603"
R11 R49 R50: "RES, 100k ohm, 1%, 0.1W, 0603"
R12 R36: "RES, 2.2 ohm, 5%, 0.125W, 0805"
R13 R16 R37: "RES, 36.5k ohm, 1%, 0.1W, 0603"
R15: "RES, 7.68k ohm, 1%, 0.1W, 0603"
R18: "RES, 68.1k ohm, 1%, 0.1W, 0603"
R19: "RES, 750 ohm, 1%, 0.1W, 0603"
R20: "RES, 51.1k ohm, 1%, 0.125W, 0805"
R21 R39 R55: "RES, 825 ohm, 1%, 0.125W, 0805"
R22 R23 R24 R27 R31 R33: "RES, 49.9 ohm, 1%, 0.1W, 0603"
R42: "RES, 30.5k ohm, 0.5%, 0.1W, 0603"
R43: "RES, 10.0k ohm, 1%, 0.1W, 0603"
R44: "RES, 1.00k ohm, 1%, 0.1W, 0603"
R45 R46: "RES, 2.00k ohm, 1%, 0.1W, 0603"
R47: "RES, 820 ohm, 1%, 0.1W, 0603"
R48: "RES, 56.0 ohm, 1%, 0.1W, 0603"
R53 R54 R58 R59: "RES, 0 ohm, 5%, 0.25W, 1206"
TP1 TP3: library part 5010, "Test Point, Multipurpose, Red, TH"
TP2 TP7 TP8 TP9: library part 5012, "Test Point, Multipurpose, White, TH"
TP4 TP5: library part 5011, "Test Point, Multipurpose, Black, TH"
TP14: library part 5009, "Test Point, Compact, Yellow, TH"
U1 U2: library part LM5122
U3: "Series of Adjustable Micropower Voltage Regulators, 8-pin LLP"
U4: "IC, Op-Amp Low Voltage Rail-to-Rail Output, 130 µA Typ."
ZZ1: library part AssemblyNoteLabel
ZZ2 ZZ3 ZZ4: library part AssemblyNote

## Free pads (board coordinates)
  round 60 hole 30: 0(150,3525) 0(300,3050) 0(360,3760) 0(360,4420) 0(400,1700) 0(800,1875) 0(1070,1240) 0(1150,1550) 0(1275,2400) 0(1650,3775) 0(2340,5760) 0(2340,5840) 0(3187,527) 0(3300,3700) 0(3425,1800) 0(3550,775) 0(3550,1075) 0(4225,1200) 0(4400,5760) 0(4400,5840) 0(4550,4600) 0(4800,4600) 0(5260,3100) 0(5260,3200) 0(5325,1175) 0(5350,3625) 0(6175,3050) 0(6375,3050) 0(6900,1650) 0(6900,2250) 0(6900,3400) 1(150,3400) 1(360,4120) 1(400,3050) 1(475,1525) 1(480,3760) 1(800,1700) 1(1300,1550) 1(1500,2400) 1(1775,3775) 1(2340,5660) 1(3425,1500) 1(3425,3700) 1(3625,775) 1(4225,1075) 1(4400,5660) 1(4897,809) 1(5050,4600) 1(5260,3020) 1(5260,3280) 1(5350,3525) 1(5525,1225) 1(6900,1450) 1(6900,2050) 1(6900,3200) 2(150,3225) 2(480,4120) 2(500,3050) 2(625,1525) 2(640,3760) 2(1075,1875) 2(1300,1400) 2(1725,2400) 2(1925,3775) 2(2340,5560) 2(3425,1075) 2(3425,3800) 2(3650,1075) 2(4225,1000) 2(4400,5560) 2(5260,2940) 2(5260,3360) 2(5300,4600) 2(5350,3425) 2(5575,1450) 2(6275,3050) 2(6900,1850) 2(6900,2800) 2(6900,2950) 3(150,3050) 3(325,1325) 3(600,3050) 3(640,4120) 3(780,3760) 3(1075,1700) 3(1450,1450) 3(1750,3100) 3(2075,3775) 3(2340,5460) 3(3300,3800) 3(3425,775) 3(4225,800) 3(4400,5460) 3(5200,3320) 3(5225,3425) 3(5260,2860) 3(5550,4600) 3(5800,1450) 3(6900,2650) 4(150,2825) 4(350,1125) 4(675,1375) 4(700,3050) 4(780,4120) 4(900,3760) 4(1750,2975) 4(2200,3775) 4(2340,5360) 4(3300,3950) 4(4225,700) 4(4225,1775) 4(4400,5360) 4(5200,3240) 4(5225,3525) 4(5260,2780) 4(5800,4600) 4(5850,1675) 4(6475,3050) 4(6900,2450) 5(150,2575) 5(500,1175) 5(800,3050) 5(850,1375) 5(900,4120) 5(1750,2850) 5(1925,3675) 5(2340,5260) 5(3425,3950) 5(4225,575) 5(4225,1675) 5(4400,3180) 5(4400,5260) 5(5225,1725) 5(5225,3625) 5(5340,2900) 5(6050,4600) 5(6575,3050) 6(150,2350) 6(575,1025) 6(675,1125) 6(1660,4120) 6(1750,2725) 6(2075,3675) 6(2340,5160) 6(2760,4380) 6(3425,4100) 6(3960,4360) 6(4225,1500) 6(4275,400) 6(4400,5160) 6(4600,3180) 6(5300,3575) 6(5340,2820) 6(5425,1750) 6(6300,4600) 7(150,2100) 7(800,2050) 7(850,1125) 7(1800,4120) 7(2200,3675) 7(2340,5060) 7(2760,4280) 7(3300,4100) 7(3960,4260) 7(4400,5060) 7(4720,3180) 7(5275,3475) 7(5340,2740) 7(5525,1950) 7(6550,4600) 7(6675,3050) 7(6900,1200) 8(150,1900) 8(1075,2050) 8(1925,3575) 8(1940,4120) 8(2340,4960) 8(2760,4180) 8(3294,1800) 8(3300,4250) 8(3960,4160) 8(4400,4960) 8(4720,3080) 8(5340,2660) 8(5725,2000) 8(6800,4600) 8(6900,1025) 9(150,1500) 9(1925,3475) 9(2080,4120) 9(2340,4860) 9(2760,4080) 9(3293,1650) 9(3425,4250) 9(3960,4060) 9(4400,4860) 9(4720,2980) 9(5340,2580) 9(5800,2200) 9(6850,4350) 9(6900,875) 10(150,1300) 10(1925,3375) 10(2220,4120) 10(2340,4760) 10(2760,3980) 10(3296,1500) 10(3425,4400) 10(3960,3960) 10(4400,4760) 10(4720,2880) 10(4725,2550) 10(5340,2500) 10(6850,4100) 10(6875,650) 11(150,1075) 11(1700,2900) 11(2025,3375) 11(2340,4660) 11(2760,3880) 11(3300,4400) 11(3600,1800) 11(3960,3860) 11(4180,4120) 11(4400,4660) 11(4720,2780) 11(5225,2550) 11(6525,325) 11(6850,3850) 12(150,825) 12(1700,2780) 12(2025,3475) 12(2325,2550) 12(2340,4560) 12(2760,3780) 12(3350,4575) 12(3600,1650) 12(4320,4120) 12(4400,4560) 12(5100,3200) 12(6850,3600) 13(175,550) 13(1700,2660) 13(2025,3575) 13(2775,2550) 13(3375,4675) 13(3600,1500) 13(4460,4120) 13(5100,3320) 13(6750,2950) 14(475,325) 14(1800,3375) 14(3350,4800) 14(4620,4120) 14(5220,3720) 14(6750,2800) 15(375,525) 15(1675,3375) 15(3375,4925) 15(4780,4120) 15(5300,3720) 15(6750,2650) 16(850,325) 16(1750,3225) 16(3350,5050) 16(4960,4120) 16(5400,3720) 16(6750,2450) 17(300,2950) 17(1200,325) 17(2875,2950) 17(3350,5375) 17(5140,4120) 17(5500,3720) 18(300,2750) 18(1550,325) 18(2875,2875) 18(3375,5500) 18(5340,4120) 18(5500,3820) 19(300,2550) 19(1825,325) 19(2875,2800) 19(3350,5625) 19(5400,3820) 19(5580,4120) 20(300,2350) 20(2125,325) 20(2875,2725) 20(3375,5750) 20(5300,3820) 20(5820,4120) 21(2200,4600) 21(2400,325) 21(2875,2650) 21(3350,5875) 21(5220,3820) 21(6020,4120) 22(1950,4600) 22(2650,325) 22(2875,2575) 22(4675,325) 22(6200,4120) 23(1700,4600) 23(2875,325) 23(2950,2925) 23(4875,325) 23(6380,4120) 24(1450,4600) 24(1760,2600) 24(2950,2850) 24(5075,325) 24(5400,75) 25(1200,4600) 25(1700,2520) 25(2950,2775) 25(5275,325) 25(5725,75) 26(950,4600) 26(1760,2480) 26(2950,2700) 26(3825,1775) 26(5950,75) 27(700,4600) 27(2320,3120) 27(2950,2625) 27(3825,1675) 27(6225,75) 28(450,4600) 28(1925,3275) 28(2320,3020) 28(3825,1500) 29(200,4600) 29(1675,3475) 29(2320,2920) 29(3825,1200) 30(125,4350) 30(1675,3575) 30(2320,2820) 30(3825,1075) 31(125,4100) 31(1800,3575) 31(2320,2720) 31(3825,1000) 32(125,3850) 32(1800,3475) 32(3825,800) 32(4320,3700) 33(125,3650) 33(1750,3525) 33(3825,700) 33(4460,3700) 34(1725,3425) 34(3825,400) 34(4620,3700) 35(3825,300) 35(4780,3700) 36(3825,200) 36(4960,3700) 37(3275,75) 37(4400,3500) 38(4540,3500) 39(4700,3500) 40(4880,3500) 41(2920,2400) 42(3160,2400) 43(3400,2400) 44(3640,2400) 45(2220,4420) 46(6680,4420) 47(6680,3680)
  round 40 hole 30: 0(330,3550) 0(6240,3560) 1(400,3550) 1(6310,3560) 2(480,3550) 2(6390,3560) 3(560,3550) 3(6470,3560) 4(640,3550) 4(6550,3560) 5(730,3550) 5(6640,3560) 6(330,3490) 6(6240,3500) 7(400,3490) 7(6310,3500) 8(480,3490) 8(6390,3500) 9(560,3490) 9(6470,3500) 10(640,3490) 10(6550,3500) 11(730,3490) 11(6640,3500) 12(330,3420) 12(6240,3430) 13(400,3420) 13(6310,3430) 14(480,3420) 14(6390,3430) 15(560,3420) 15(6470,3430) 16(640,3420) 16(6550,3430) 17(730,3420) 17(6640,3430)
  round 25 hole 15: 0(1804,1238) 0(1940,1281) 0(1940,1828) 0(2088,2392) 0(2094.52,1299.12) 0(2111,1968) 0(2120,1760) 0(2121,3357) 0(2122.37,991.18) 0(2143.52,1599.12) 0(2146,1701) 0(2152,2196.69) 0(2231,1828) 0(2246.52,1586.12) 0(2269.56,3357.44) 0(2359.68,3307.44) 0(2379.56,3355.44) 0(2546,1398) 0(2594.56,3410.44) 0(2623,1239) 0(2626,2392) 0(2645,1968) 0(2677.52,795.43) 0(2690,2198) 0(4039,2829.6) 0(4072,3120) 0(4135,2796) 0(4135,2920) 0(4140,2645) 0(4377,1748) 0(4481,2390) 0(4505,1962) 0(4545,2191.98) 0(4549,1597.68) 0(4634,1809.68) 0(4716,1594.68) 0(4824,1297) 0(4831,1521.68) 0(4930,1735.68) 0(5005,1736) 0(5030,2390) 0(5052,1962) 0(5092,2192) 1(2182.37,991.18) 1(2419,1523) 1(2772.52,469.43) 2(4526,991.68) 3(940,2848) 3(975,2848) 3(4586,991.68) 3(6016,2860) 3(6051,2860)
  round 20 hole 10: 0(1880,3110) 0(2230,3110) 0(2272.32,1229.5) 0(2297.32,1207.5) 0(2315,1597.08) 0(2322.32,1229.5) 0(2354.52,1599.12) 0(2383.52,929.12) 0(2389.52,1760.12) 0(2440,2730) 0(2515,886) 0(2544,933) 0(2547.52,1826.12) 0(2740,2730) 0(4677,1219) 1(1900,3090) 1(2210,3090) 1(2420,2750) 1(2760,2750) 1(4700,1199) 2(1880,3070) 2(2230,3070) 2(2440,2770) 2(2740,2770) 2(4727,1219) 3(1900,3050) 3(2210,3050) 3(2420,2790) 3(2760,2790) 4(1880,3030) 4(2230,3030) 4(2440,2810) 4(2740,2810) 5(1900,3010) 5(2210,3010) 5(2420,2830) 5(2760,2830) 6(1880,2990) 6(2230,2990) 6(2440,2850) 6(2740,2850) 7(1900,2970) 7(2210,2970) 7(2420,2870) 7(2760,2870) 8(1880,2950) 8(2230,2950) 8(2440,2890) 8(2740,2890) 9(1900,2930) 9(2210,2930) 9(2420,2910) 9(2760,2910) 10(1880,2910) 10(2230,2910) 10(2440,2930) 10(2740,2930) 11(1900,2890) 11(2210,2890) 11(2420,2950) 11(2760,2950) 12(1880,2870) 12(2230,2870) 12(2440,2970) 12(2740,2970) 13(1900,2850) 13(2210,2850) 13(2420,2990) 13(2760,2990) 14(1880,2830) 14(2230,2830) 14(2440,3010) 14(2740,3010) 15(1900,2810) 15(2210,2810) 15(2420,3030) 15(2760,3030) 16(1880,2790) 16(2230,2790) 16(2440,3050) 16(2740,3050) 17(1900,2770) 17(2210,2770) 17(2420,3070) 17(2760,3070) 18(1880,2750) 18(2230,2750) 18(2440,3090) 18(2740,3090) 19(1900,2730) 19(2210,2730) 19(2420,3110) 19(2760,3110) 20(2570,3110) 21(2600,3110) 22(2600,3080) 23(2570,3080) 24(2570,3050) 25(2600,3050) 26(2600,3020) 27(2570,3020) 28(2570,2990) 29(2600,2990) 30(2600,2960) 31(2570,2960) 32(2570,2930) 33(2600,2930) 34(2600,2900) 35(2570,2900) 36(2570,2870) 37(2600,2870) 38(2600,2840) 39(2570,2840) 40(2570,2810) 41(2600,2810) 42(2600,2780) 43(2570,2780) 44(2570,2750) 45(2600,2750) 46(2040,3112) 47(2070,3112) 48(2070,3082) 49(2040,3082) 50(2040,3052) 51(2070,3052) 52(2070,3022) 53(2040,3022) 54(2040,2992) 55(2070,2992) 56(2070,2962) 57(2040,2962) 58(2040,2932) 59(2070,2932) 60(2070,2902) 61(2040,2902) 62(2040,2872) 63(2070,2872) 64(2070,2842) 65(2040,2842) 66(2040,2812) 67(2070,2812) 68(2070,2782) 69(2040,2782) 70(2040,2752) 71(2070,2752) 72(4610,2730) 73(4630,2750) 74(4610,2770) 75(4630,2790) 76(4610,2810) 77(4630,2830) 78(4610,2850) 79(4630,2870) 80(4610,2890) 81(4630,2910) 82(4610,2930) 83(4630,2950) 84(4610,2970) 85(4630,2990) 86(4610,3010) 87(4630,3030) 88(4610,3050) 89(4630,3070) 90(4610,3090) 91(4630,3110) 92(4290,2730) 93(4270,2750) 94(4290,2770) 95(4270,2790) 96(4290,2810) 97(4270,2830) 98(4290,2850) 99(4270,2870) 100(4290,2890) 101(4270,2910) 102(4290,2930) 103(4270,2950) 104(4290,2970) 105(4270,2990) 106(4290,3010) 107(4270,3030) 108(4290,3050) 109(4270,3070) 110(4290,3090) 111(4270,3110) 112(4840,2730) 113(4820,2750) 114(4840,2770) 115(4820,2790) 116(4840,2810) 117(4820,2830) 118(4840,2850) 119(4820,2870) 120(4840,2890) 121(4820,2910) 122(4840,2930) 123(4820,2950) 124(4840,2970) 125(4820,2990) 126(4840,3010) 127(4820,3030) 128(4840,3050) 129(4820,3070) 130(4840,3090) 131(4820,3110) 132(5160,2730) 133(5180,2750) 134(5160,2770) 135(5180,2790) 136(5160,2810) 137(5180,2830) 138(5160,2850) 139(5180,2870) 140(5160,2890) 141(5180,2910) 142(5160,2930) 143(5180,2950) 144(5160,2970) 145(5180,2990) 146(5160,3010) 147(5180,3030) 148(5160,3050) 149(5180,3070) 150(5160,3090) 151(5180,3110) 152(4460,3110) 153(4430,3110) 154(4430,3080) 155(4460,3080) 156(4460,3050) 157(4430,3050) 158(4430,3020) 159(4460,3020) 160(4460,2990) 161(4430,2990) 162(4430,2960) 163(4460,2960) 164(4460,2930) 165(4430,2930) 166(4430,2900) 167(4460,2900) 168(4460,2870) 169(4430,2870) 170(4430,2840) 171(4460,2840) 172(4460,2810) 173(4430,2810) 174(4430,2780) 175(4460,2780) 176(4460,2750) 177(4430,2750) 178(5010,3110) 179(4980,3110) 180(4980,3080) 181(5010,3080) 182(5010,3050) 183(4980,3050) 184(4980,3020) 185(5010,3020) 186(5010,2990) 187(4980,2990) 188(4980,2960) 189(5010,2960) 190(5010,2930) 191(4980,2930) 192(4980,2900) 193(5010,2900) 194(5010,2870) 195(4980,2870) 196(4980,2840) 197(5010,2840) 198(5010,2810) 199(4980,2810) 200(4980,2780) 201(5010,2780) 202(5010,2750) 203(4980,2750)
  round 23 hole 13: 0(2061,2089) 1(2594,2089) 2(4453,2084) 3(4999,2084)
  round 24 hole 12: 0(3096.08,3402.37) 204(3030,3580) 205(3060,3550) 206(3030,3520) 207(3060,3490) 208(3030,3460) 209(3060,3430) 210(3030,3400) 211(3060,3370) 212(3030,3340) 213(3060,3310) 214(3030,3280) 215(3060,3250) 216(3720,3580) 217(3690,3550) 218(3720,3520) 219(3690,3490) 220(3720,3460) 221(3690,3430) 222(3720,3400) 223(3690,3370) 224(3720,3340) 225(3690,3310) 226(3720,3280) 227(3690,3250) 228(3720,3220) 229(3030,3220) 230(3230,3580) 231(3200,3550) 232(3230,3520) 233(3200,3490) 234(3230,3460) 235(3200,3430) 236(3230,3400) 237(3200,3370) 238(3230,3340) 239(3200,3310) 240(3230,3280) 241(3200,3250) 242(3230,3220) 243(3510,3580) 244(3540,3550) 245(3510,3520) 246(3540,3490) 247(3510,3460) 248(3540,3430) 249(3510,3400) 250(3540,3370) 251(3510,3340) 252(3540,3310) 253(3510,3280) 254(3540,3250) 255(3510,3220) 256(3100,3520) 257(3100,3460) 259(3110,3340) 260(3110,3280) 261(3160,3520) 262(3160,3460) 263(3160,3400) 264(3160,3340) 265(3160,3280) 266(3580,3520) 267(3580,3460) 268(3580,3400) 269(3580,3340) 270(3580,3280) 271(3650,3280) 272(3650,3340) 273(3650,3400) 274(3650,3460) 275(3650,3520)
  round 22 hole 12: 0(4566,1650) 0(4652,1597)

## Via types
v1: diameter 20, hole 10, Top Layer to Bottom Layer, 29 vias

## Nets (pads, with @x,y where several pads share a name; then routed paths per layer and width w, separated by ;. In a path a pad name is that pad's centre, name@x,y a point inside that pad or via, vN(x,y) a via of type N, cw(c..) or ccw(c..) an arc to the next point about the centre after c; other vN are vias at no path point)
+5V: C52.1 pad.0@2677.52,795.43 pad.1@2772.52,469.43 R41.2 R42.2 R46.2 U3.1 U4.5 | length 587.4
  Top Layer w20: R41.2@2721.02,469.43 2747.28,495.69 U3.1@2747.28,579.63
  Top Layer w25: pad.0@2677.52,795.43 R42.2@2727.03,795.43 ; R41.2@2721.02,469.43 pad.1@2772.52,469.43
  Bottom Layer w25: pad.0@2677.52,795.43 2677.52,564.43 pad.1@2772.52,469.43
BODE: pad.0@1804,1238 pad.0@2623,1239 R20.2 R21.2 TP7.1 | length 1191.1
  Top Layer w30: R21.2@1745,1238 pad.0@1804,1238 ; R20.2@2623,1177.59 pad.0@2623,1239
  Top Layer w40: R21.2@1744,1237 1744,1132 TP7.1@1826,1050
  Bottom Layer w15: pad.0@1804,1238 2115.38,1238 2153,1275.62 2586.38,1275.62 pad.0@2623,1239
BST1: C15.2 C27.1 D1.1 pad.0@2120,1760 pad.0@2359.68,3307.44 Q8.3 U1.20 | length 2335.8
  Top Layer w23: Q8.3@2304.16,3452.44 2313.93,3442.67 2313.93,3388.52 2331.56,3370.9 2331.56,3335.56 pad.0@2359.68,3307.44 2417.56,3307.44 2457.56,3347.44 C27.1@2457.56,3442.94
  Bottom Layer w23: pad.0@2120,1760 2120,1780 2105,1795 2105,1906.12 2063,1948.12 2063,2020.53 2014,2069.53 2014,2108.47 2041.53,2136 2063,2136 2063,2219.22 2041,2241.22 2041,2371.12 2040,2372.12 2040,2411.88 2063,2434.88 2063,2706.5 2021.15,2706.5 1994.5,2733.15 1994.5,3130.85 2021.15,3157.5 2209.74,3157.5 pad.0@2359.68,3307.44
BST2: C44.1 C45.2 D3.1 pad.0@4039,2829.6 pad.0@4377,1748 Q15.3 U2.20 | length 1758.1
  Top Layer w23: pad.0@4039,2829.6 4046.14,2836.74 4095.87,2836.74 4098.5,2839.37 4102.92,2839.37 4135.54,2872 4154.88,2872 4183,2900.12 4183,2949 4149,2983 C44.1@4039.5,2983 ; pad.0@4377,1749.68 D3.1@4533.81,1749.68
  Bottom Layer w23: pad.0@4039,2829.6 4039,2825.53 4087,2777.53 4087,2776.12 4092,2771.12 4092,2033 pad.0@4377,1748
COMP: C23.2 C24.2 pad.0@2546,1398 pad.0@4831,1521.68 pad.1@2419,1523 U1.11 U2.11 | length 2615.9
  Top Layer w12: U2.11@4777.16,1521.2 pad.0@4830.52,1521.2
  Top Layer w14: U1.11@2371.47,1522.71 pad.1@2419,1522.71
  Bottom Layer w14: pad.1@2419,1523 2421,1523 pad.0@2546,1398 4404.65,1398 4528.33,1521.68 pad.0@4831,1521.68
CSN1: C16.1 R4.1 U1.3 | length 233.1
  Top Layer w14: C16.1@2122.37,1154.18 C16.1@2124.37,1156.18 2140.52,1172.34 2140.52,1202.12 2192.34,1253.93 U1.3@2192.34,1298.3
  Top Layer w25: R4.1@2122.37,1094.18 C16.1@2122.37,1154.18
CSN2: C46.1 R29.1 U2.3 | length 225.5
  Top Layer w12: C46.1@4528,1160 4546,1178 4546,1199.79 4598.03,1251.82 U2.3@4598.03,1296.79
  Top Layer w25: R29.1@4528,1100.33 C46.1@4528,1160
CSP1: C16.2 R3.1 U1.4 | length 230.8
  Top Layer w14: C16.2@2180.37,1156.18 2164.52,1172.03 2164.52,1192.12 2217.83,1245.42 U1.4@2217.83,1298.3
  Top Layer w25: R3.1@2182.37,1094.18 C16.2@2182.37,1154.18
CSP2: C46.2 R28.1 U2.4 | length 225.8
  Top Layer w12: C46.2@4584,1160 4568,1176 4568,1190.68 4623.62,1246.3 U2.4@4623.62,1296.79
  Top Layer w25: R28.1@4584,1100.67 C46.2@4584,1160
FB: C23.1 R18.1 R19.1 R20.1 R48.2 U1.10
GND: C2.2 C3.2 C4.2 C5.2 C6.2 C7.2 C8.2 C9.2 C10.2 C11.2 C12.2 C13.2 C14.2 C17.1 C25.2 C26.2 C29.2 C30.2 C31.2 C32.2 C33.2 C34.2 C35.2 C36.2 C37.2 C38.2 C39.2 C40.2 C43.2 C47.1 J2.1 J3.1 pad.0@300,3050 pad.0@400,1700 pad.0@800,1875 pad.0@1150,1550 pad.0@2340,5760 pad.0@2340,5840 pad.0@3187,527 pad.0@3425,1800 pad.0@3550,775 pad.0@3550,1075 pad.0@4400,5760 pad.0@4400,5840 pad.0@4550,4600 pad.0@4800,4600 pad.0@5325,1175 pad.0@6175,3050 pad.0@6375,3050 pad.1@400,3050 pad.1@475,1525 pad.1@800,1700 pad.1@1300,1550 pad.1@2340,5660 pad.1@3425,1500 pad.1@3625,775 pad.1@4400,5660 pad.1@4897,809 pad.1@5050,4600 pad.1@5525,1225 pad.2@500,3050 pad.2@625,1525 pad.2@1075,1875 pad.2@1300,1400 pad.2@2340,5560 pad.2@3425,1075 pad.2@3650,1075 pad.2@4400,5560 pad.2@5300,4600 pad.2@5575,1450 pad.2@6275,3050 pad.3@325,1325 pad.3@600,3050 pad.3@1075,1700 pad.3@1450,1450 pad.3@2340,5460 pad.3@3425,775 pad.3@4400,5460 pad.3@5550,4600 pad.3@5800,1450 pad.4@350,1125 pad.4@675,1375 pad.4@700,3050 pad.4@2340,5360 pad.4@4400,5360 pad.4@5800,4600 pad.4@5850,1675 pad.4@6475,3050 pad.5@500,1175 pad.5@800,3050 pad.5@850,1375 pad.5@2340,5260 pad.5@4400,5260 pad.5@5225,1725 pad.5@6050,4600 pad.5@6575,3050 pad.6@575,1025 pad.6@675,1125 pad.6@2340,5160 pad.6@2760,4380 pad.6@3960,4360 pad.6@4400,5160 pad.6@5425,1750 pad.6@6300,4600 pad.7@800,2050 pad.7@850,1125 pad.7@2340,5060 pad.7@2760,4280 pad.7@3960,4260 pad.7@4400,5060 pad.7@5525,1950 pad.7@6550,4600 pad.7@6675,3050 pad.8@1075,2050 pad.8@2340,4960 pad.8@2760,4180 pad.8@3294,1800 pad.8@3960,4160 pad.8@4400,4960 pad.8@5725,2000 pad.8@6800,4600 pad.9@2340,4860 pad.9@2760,4080 pad.9@3293,1650 pad.9@3960,4060 pad.9@4400,4860 pad.9@5800,2200 pad.9@6850,4350 pad.10@2340,4760 pad.10@2760,3980 pad.10@3296,1500 pad.10@3960,3960 pad.10@4400,4760 pad.10@4725,2550 pad.10@6850,4100 pad.11@2340,4660 pad.11@2760,3880 pad.11@3600,1800 pad.11@3960,3860 pad.11@4400,4660 pad.11@5225,2550 pad.11@6850,3850 pad.12@2325,2550 pad.12@2340,4560 pad.12@2760,3780 pad.12@3600,1650 pad.12@4400,4560 pad.12@6850,3600 pad.13@2775,2550 pad.13@3600,1500 pad.13@6750,2950 pad.14@6750,2800 pad.15@6750,2650 pad.16@6750,2450 pad.17@300,2950 pad.18@300,2750 pad.19@300,2550 pad.20@300,2350 pad.21@2200,4600 pad.22@1950,4600 pad.23@1700,4600 pad.24@1450,4600 pad.25@1200,4600 pad.26@950,4600 pad.27@700,4600 pad.28@450,4600 pad.29@200,4600 pad.30@125,4350 pad.31@125,4100 pad.32@125,3850 pad.33@125,3650 Q2.3 Q3.3 Q5.3 Q7.3 Q12.3 Q13.3 Q16.3 Q17.3 TP4.1 TP5.1 U1.15 U2.15 | length 169
  Top Layer w25: pad.0@3187,527 3187,609 ; pad.1@4897,809 4897,896
HO1: pad.0@2121,3357 pad.0@2143.52,1599.12 R5.2 U1.19 | length 2214.1
  Top Layer w14: pad.0@2143.52,1599.12 2166.75,1575.89 U1.19@2166.75,1522.71
  Top Layer w25: pad.0@2121,3357 R5.2@2167,3357
  Bottom Layer w25: pad.0@2121,3357 1957.23,3193.23 1897.47,3193.23 1833.5,3129.26 1833.5,2730.74 1904,2660.24 1904,1933.3 1989,1848.3 1989,1807.7 1988,1806.7 1988,1795.88 1983,1790.88 1983,1751.12 1988,1746.12 1988,1692 2080.88,1599.12 pad.0@2143.52,1599.12
HO2: pad.0@4140,2645 pad.0@4549,1597.68 R35.2 U2.19 | length 1349.9
  Top Layer w14: pad.0@4549,1597.68 4572.44,1574.25 U2.19@4572.44,1521.2
  Top Layer w25: pad.0@4140,2645 R35.2@4140,2692
  Bottom Layer w25: pad.0@4140,2645 4140,2067 4495,1712 4495,1651.69 pad.0@4549,1597.68
LIN1: L1.1 NT3.2 R2.1 R52.2 | length 652.7
  Top Layer w15: L1.1@1299,3542 1348,3493 NT3.2@1348,3138
  Top Layer w25: R52.2@973.99,3214.85 R2.1@973.99,3443.22
LIN2: L2.2 NT5.2 R26.1 R57.2 | length 771.6
  Top Layer w15: NT5.2@5633,3129 5633,3515 5651,3533 L2.2@5794.81,3533
  Top Layer w25: R57.2@6016,3223.5 R26.1@6016,3439.87
LO1: pad.0@2111,1968 pad.0@2246.52,1586.12 pad.0@2645,1968 R7.1 R9.2 U1.16 | length 1297.3
  Top Layer w14: U1.16@2243.52,1522.71 2243.52,1583.11 pad.0@2246.52,1586.12
  Top Layer w23: pad.0@2111,1968 R7.1@2160.69,1968 ; pad.0@2645,1968 R9.2@2693,1968
  Bottom Layer w23: pad.0@2111,1968 2194.84,1884.16 2194.84,1637.8 pad.0@2246.52,1586.12 2246.52,1734.52 2305,1793 2470,1793 2470.12,1793.12 2561.19,1793.12 2580.52,1812.45 2580.52,1903.52 pad.0@2645,1968
LO2: pad.0@4505,1962 pad.0@4652,1597 pad.0@5052,1962 R30.1 R32.2 U2.16 | length 1235.3
  Top Layer w14: U2.16@4649.21,1521.2 4649.21,1594.21 pad.0@4652,1597
  Top Layer w23: pad.0@4505,1962 R30.1@4552,1961.98 ; pad.0@5052,1962 R32.2@5100,1962
  Bottom Layer w23: pad.0@4505,1962 4600,1867 4600,1722.47 4652,1670.47 pad.0@4652,1597 4756.68,1701.68 4944.09,1701.68 4964,1721.6 4964,1871.01 pad.0@5052,1959.01
MODE1: pad.0@2354.52,1599.12 pad.0@2389.52,1760.12 R14.1 R17.2 U1.13 | length 380.6
  Top Layer w12: U1.13@2320.29,1522.71 2320.29,1564.88 pad.0@2354.52,1599.12
  Top Layer w20: pad.0@2389.52,1760.12 R17.2@2438.03,1760.12
  Top Layer w35: R17.2@2438.03,1760.12 R14.1@2438.03,1826.12
  Bottom Layer w20: pad.0@2354.52,1599.12 2354.52,1725.12 pad.0@2389.52,1760.12
MODE2: R38.1 R40.2 U2.13 | length 252.4
  Top Layer w14: U2.13@4725.98,1521.2 4725.98,1562.18 4757.5,1593.7 4757.5,1609.67 R40.2@4817.51,1669.68
  Top Layer w35: R40.2@4817.51,1669.68 R38.1@4817.51,1735.68
NetC1_1: C1.1 R1.1 | length 95.4
  Top Layer w50: R1.1@3059.55,3083 C1.1@3155,3083
NetC24_1: C24.1 R18.2 | length 79.5
  Top Layer w30: R18.2@2501.02,1256.42 2527.42,1256.42 C24.1@2565,1294
NetC28_1: C28.1 R25.1 | length 106.4
  Top Layer w50: C28.1@3813,3679 R25.1@3919.45,3679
